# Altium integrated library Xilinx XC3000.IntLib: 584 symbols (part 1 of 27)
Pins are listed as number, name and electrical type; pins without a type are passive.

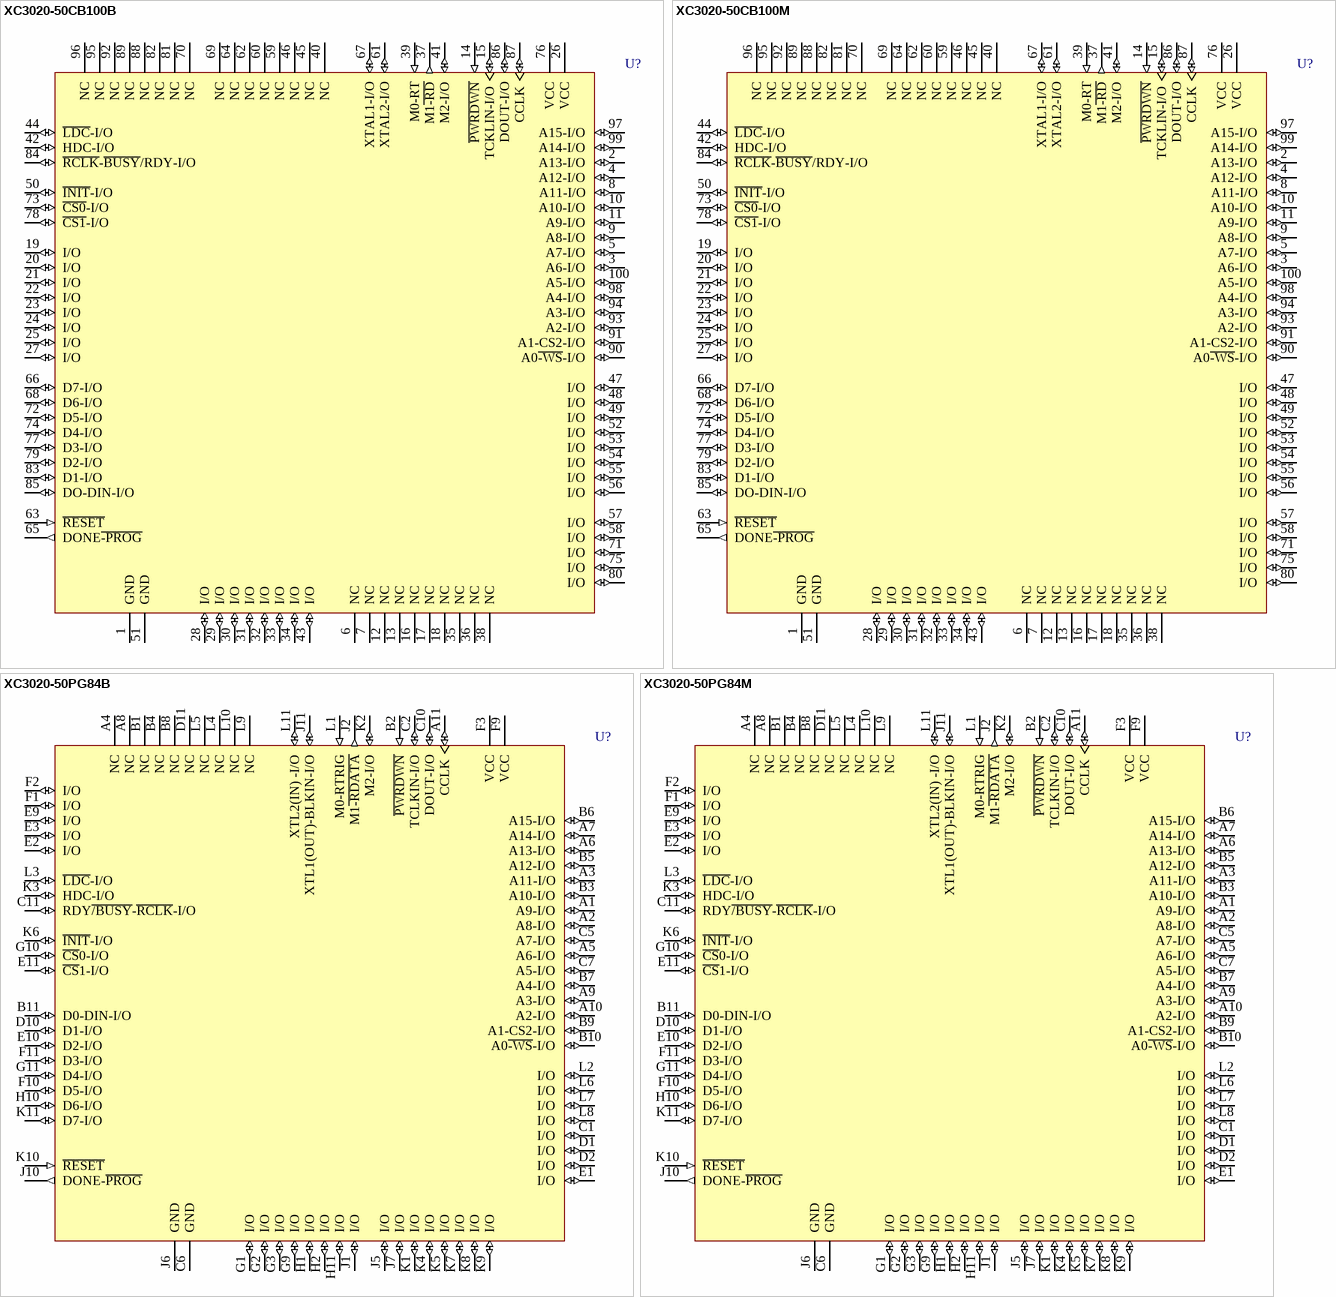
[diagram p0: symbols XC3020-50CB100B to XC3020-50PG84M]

## XC3020-50CB100B
designator U?
Logic Cell Array with 64 CLBs, with 64 I/O Pins, 100-Pin CQFP, Military Class B Grade; ComponentAvailability: Not for New Design
footprint CB100_N (CQFP, 100-Leads, Body 19x19mm; Pitch 0.635mm, Gullwing Leadform, IPC Medium Density)
footprint CB100_L (CQFP, 100-Leads, Body 19x19mm; Pitch 0.635mm, Gullwing Leadform, IPC High Density)
footprint CB100_M (CQFP, 100-Leads, Body 19x19mm; Pitch 0.635mm, Gullwing Leadform, IPC Low Density)
3D model XC3020-CB100 (100-Pin Ceramic Brazed Quad Flat Pack (CB100))
pins: 1 GND (power), 2 A13-I/O (io), 3 A6-I/O (io), 4 A12-I/O (io), 5 A7-I/O (io), 6 NC, 7 NC, 8 A11-I/O (io), 9 A8-I/O (io), 10 A10-I/O (io), 11 A9-I/O (io), 12 NC, 13 NC, 14 ~{PWRDWN} (in), 15 TCKLIN-I/O (io), 16 NC, 17 NC, 18 NC, 19 I/O (io), 20 I/O (io), 21 I/O (io), 22 I/O (io), 23 I/O (io), 24 I/O (io), 25 I/O (io), 26 VCC (power), 27 I/O (io), 28 I/O (io), 29 I/O (io), 30 I/O (io), 31 I/O (io), 32 I/O (io), 33 I/O (io), 34 I/O (io), 35 NC, 36 NC, 37 M1~{-RD} (out), 38 NC, 39 M0-RT (in), 40 NC, 41 M2-I/O (io), 42 HDC-I/O (io), 43 I/O (io), 44 ~{LDC}-I/O (io), 45 NC, 46 NC, 47 I/O (io), 48 I/O (io), 49 I/O (io), 50 ~{INIT}-I/O (io), 51 GND (power), 52 I/O (io), 53 I/O (io), 54 I/O (io), 55 I/O (io), 56 I/O (io), 57 I/O (io), 58 I/O (io), 59 NC, 60 NC, 61 XTAL2-I/O (io), 62 NC, 63 ~{RESET} (in), 64 NC, 65 DONE~{-PROG} (out), 66 D7-I/O (io), 67 XTAL1-I/O (io), 68 D6-I/O (io), 69 NC, 70 NC, 71 I/O (io), 72 D5-I/O (io), 73 ~{CS0}-I/O (io), 74 D4-I/O (io), 75 I/O (io), 76 VCC (power), 77 D3-I/O (io), 78 ~{CS1}-I/O (io), 79 D2-I/O (io), 80 I/O (io), 81 NC, 82 NC, 83 D1-I/O (io), 84 ~{RCLK}-~{BUSY}/RDY-I/O (io), 85 DO-DIN-I/O (io), 86 DOUT-I/O (io), 87 CCLK (io), 88 NC, 89 NC, 90 A0~{-WS}-I/O (io), 91 A1-CS2-I/O (io), 92 NC, 93 A2-I/O (io), 94 A3-I/O (io), 95 NC, 96 NC, 97 A15-I/O (io), 98 A4-I/O (io), 99 A14-I/O (io), 100 A5-I/O (io)

## XC3020-50CB100M
designator U?
Logic Cell Array with 64 CLBs, with 64 I/O Pins, 100-Pin CQFP, Military Grade; ComponentAvailability: Not for New Design
footprint CB100_N (CQFP, 100-Leads, Body 19x19mm; Pitch 0.635mm, Gullwing Leadform, IPC Medium Density)
footprint CB100_L (CQFP, 100-Leads, Body 19x19mm; Pitch 0.635mm, Gullwing Leadform, IPC High Density)
footprint CB100_M (CQFP, 100-Leads, Body 19x19mm; Pitch 0.635mm, Gullwing Leadform, IPC Low Density)
3D model XC3020-CB100 (100-Pin Ceramic Brazed Quad Flat Pack (CB100))
pins: 1 GND (power), 2 A13-I/O (io), 3 A6-I/O (io), 4 A12-I/O (io), 5 A7-I/O (io), 6 NC, 7 NC, 8 A11-I/O (io), 9 A8-I/O (io), 10 A10-I/O (io), 11 A9-I/O (io), 12 NC, 13 NC, 14 ~{PWRDWN} (in), 15 TCKLIN-I/O (io), 16 NC, 17 NC, 18 NC, 19 I/O (io), 20 I/O (io), 21 I/O (io), 22 I/O (io), 23 I/O (io), 24 I/O (io), 25 I/O (io), 26 VCC (power), 27 I/O (io), 28 I/O (io), 29 I/O (io), 30 I/O (io), 31 I/O (io), 32 I/O (io), 33 I/O (io), 34 I/O (io), 35 NC, 36 NC, 37 M1~{-RD} (out), 38 NC, 39 M0-RT (in), 40 NC, 41 M2-I/O (io), 42 HDC-I/O (io), 43 I/O (io), 44 ~{LDC}-I/O (io), 45 NC, 46 NC, 47 I/O (io), 48 I/O (io), 49 I/O (io), 50 ~{INIT}-I/O (io), 51 GND (power), 52 I/O (io), 53 I/O (io), 54 I/O (io), 55 I/O (io), 56 I/O (io), 57 I/O (io), 58 I/O (io), 59 NC, 60 NC, 61 XTAL2-I/O (io), 62 NC, 63 ~{RESET} (in), 64 NC, 65 DONE~{-PROG} (out), 66 D7-I/O (io), 67 XTAL1-I/O (io), 68 D6-I/O (io), 69 NC, 70 NC, 71 I/O (io), 72 D5-I/O (io), 73 ~{CS0}-I/O (io), 74 D4-I/O (io), 75 I/O (io), 76 VCC (power), 77 D3-I/O (io), 78 ~{CS1}-I/O (io), 79 D2-I/O (io), 80 I/O (io), 81 NC, 82 NC, 83 D1-I/O (io), 84 ~{RCLK}-~{BUSY}/RDY-I/O (io), 85 DO-DIN-I/O (io), 86 DOUT-I/O (io), 87 CCLK (io), 88 NC, 89 NC, 90 A0~{-WS}-I/O (io), 91 A1-CS2-I/O (io), 92 NC, 93 A2-I/O (io), 94 A3-I/O (io), 95 NC, 96 NC, 97 A15-I/O (io), 98 A4-I/O (io), 99 A14-I/O (io), 100 A5-I/O (io)

## XC3020-50PG84B
designator U?
Logic Cell Array with 64 CLBs, with 64 I/O Pins, 84-Pin PGA, Military Class B Grade; ComponentAvailability: Not for New Design
footprint PG84 (PGA, 85-Leads, Body 28x28mm, Pitch 2.54mm)
3D model XC3020-PG84 (84-Pin Ceramic Pin Grid Array (PG84))
pins: A1 A9-I/O (io), A2 A8-I/O (io), A3 A11-I/O (io), A4 NC, A5 A6-I/O (io), A6 A13-I/O (io), A7 A14-I/O (io), A8 NC, A9 A3-I/O (io), A10 A2-I/O (io), A11 CCLK (io), B1 NC, B2 ~{PWRDWN} (in), B3 A10-I/O (io), B4 NC, B5 A12-I/O (io), B6 A15-I/O (io), B7 A4-I/O (io), B8 NC, B9 A1-CS2-I/O (io), B10 A0~{-WS}-I/O (io), B11 D0-DIN-I/O (io), C1 I/O (io), C2 TCLKIN-I/O (io), C5 A7-I/O (io), C6 GND (power), C7 A5-I/O (io), C10 DOUT-I/O (io), C11 RDY~{/BUSY}-~{RCLK}-I/O (io), D1 I/O (io), D2 I/O (io), D10 D1-I/O (io), D11 NC, E1 I/O (io), E2 I/O (io), E3 I/O (io), E9 I/O (io), E10 D2-I/O (io), E11 ~{CS}1-I/O (io), F1 I/O (io), F2 I/O (io), F3 VCC (power), F9 VCC (power), F10 D5-I/O (io), F11 D3-I/O (io), G1 I/O (io), G2 I/O (io), G3 I/O (io), G9 I/O (io), G10 ~{CS}0-I/O (io), G11 D4-I/O (io), H1 I/O (io), H2 I/O (io), H10 D6-I/O (io), H11 I/O (io), J1 I/O (io), J2 M1~{-RDATA} (out), J5 I/O (io), J6 GND (power), J7 I/O (io), J10 DONE-~{PROG} (out), J11 XTL1(OUT)-BLKIN-I/O (io), K1 I/O (io), K2 M2-I/O (io), K3 HDC-I/O (io), K4 I/O (io), K5 I/O (io), K6 ~{INIT}-I/O (io), K7 I/O (io), K8 I/O (io), K9 I/O (io), K10 ~{RESET} (in), K11 D7-I/O (io), L1 M0-RTRIG (in), L2 I/O (io), L3 ~{LDC}-I/O (io), L4 NC, L5 NC, L6 I/O (io), L7 I/O (io), L8 I/O (io), L9 NC, L10 NC, L11 XTL2(IN) -I/O (io)

## XC3020-50PG84M
designator U?
Logic Cell Array with 64 CLBs, with 64 I/O Pins, 84-Pin PGA, Military Grade; ComponentAvailability: Not for New Design
footprint PG84 (PGA, 85-Leads, Body 28x28mm, Pitch 2.54mm)
3D model XC3020-PG84 (84-Pin Ceramic Pin Grid Array (PG84))
pins: A1 A9-I/O (io), A2 A8-I/O (io), A3 A11-I/O (io), A4 NC, A5 A6-I/O (io), A6 A13-I/O (io), A7 A14-I/O (io), A8 NC, A9 A3-I/O (io), A10 A2-I/O (io), A11 CCLK (io), B1 NC, B2 ~{PWRDWN} (in), B3 A10-I/O (io), B4 NC, B5 A12-I/O (io), B6 A15-I/O (io), B7 A4-I/O (io), B8 NC, B9 A1-CS2-I/O (io), B10 A0~{-WS}-I/O (io), B11 D0-DIN-I/O (io), C1 I/O (io), C2 TCLKIN-I/O (io), C5 A7-I/O (io), C6 GND (power), C7 A5-I/O (io), C10 DOUT-I/O (io), C11 RDY~{/BUSY}-~{RCLK}-I/O (io), D1 I/O (io), D2 I/O (io), D10 D1-I/O (io), D11 NC, E1 I/O (io), E2 I/O (io), E3 I/O (io), E9 I/O (io), E10 D2-I/O (io), E11 ~{CS}1-I/O (io), F1 I/O (io), F2 I/O (io), F3 VCC (power), F9 VCC (power), F10 D5-I/O (io), F11 D3-I/O (io), G1 I/O (io), G2 I/O (io), G3 I/O (io), G9 I/O (io), G10 ~{CS}0-I/O (io), G11 D4-I/O (io), H1 I/O (io), H2 I/O (io), H10 D6-I/O (io), H11 I/O (io), J1 I/O (io), J2 M1~{-RDATA} (out), J5 I/O (io), J6 GND (power), J7 I/O (io), J10 DONE-~{PROG} (out), J11 XTL1(OUT)-BLKIN-I/O (io), K1 I/O (io), K2 M2-I/O (io), K3 HDC-I/O (io), K4 I/O (io), K5 I/O (io), K6 ~{INIT}-I/O (io), K7 I/O (io), K8 I/O (io), K9 I/O (io), K10 ~{RESET} (in), K11 D7-I/O (io), L1 M0-RTRIG (in), L2 I/O (io), L3 ~{LDC}-I/O (io), L4 NC, L5 NC, L6 I/O (io), L7 I/O (io), L8 I/O (io), L9 NC, L10 NC, L11 XTL2(IN) -I/O (io)

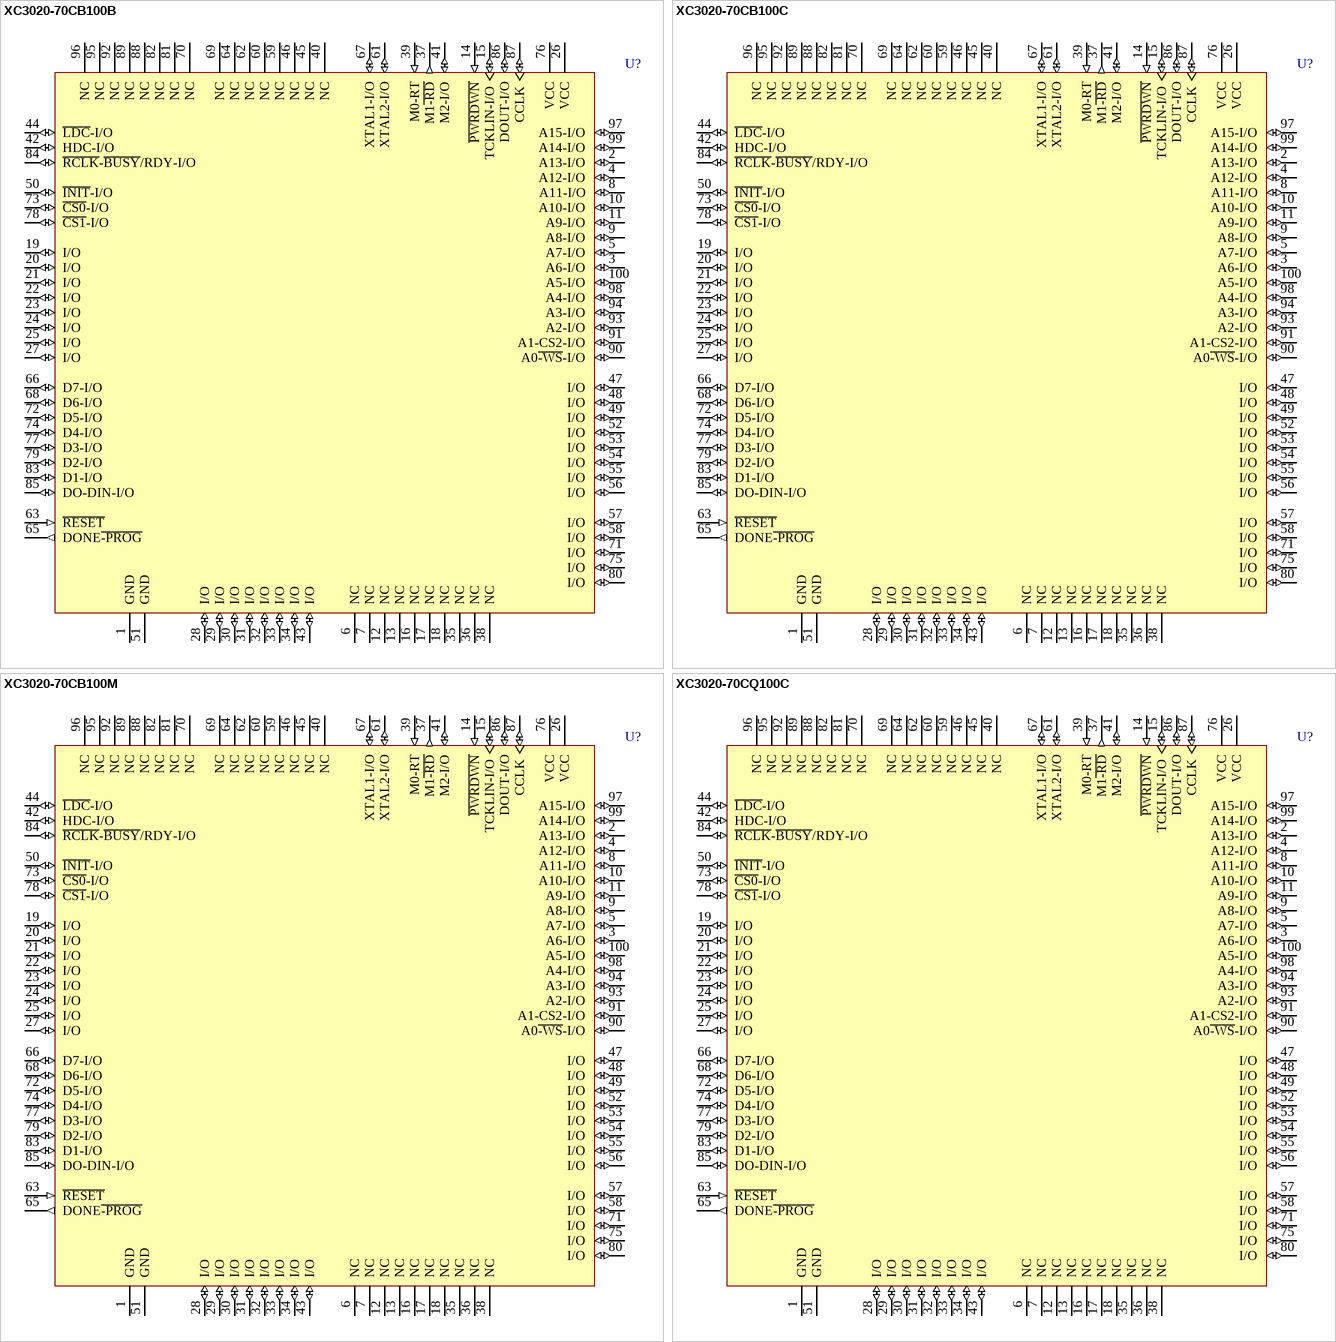
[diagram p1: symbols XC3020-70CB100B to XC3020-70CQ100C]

## XC3020-70CB100B
designator U?
Logic Cell Array with 64 CLBs, with 64 I/O Pins, 100-Pin CQFP, Military Class B Grade; ComponentAvailability: Not for New Design
footprint CB100_N (CQFP, 100-Leads, Body 19x19mm; Pitch 0.635mm, Gullwing Leadform, IPC Medium Density)
footprint CB100_L (CQFP, 100-Leads, Body 19x19mm; Pitch 0.635mm, Gullwing Leadform, IPC High Density)
footprint CB100_M (CQFP, 100-Leads, Body 19x19mm; Pitch 0.635mm, Gullwing Leadform, IPC Low Density)
3D model XC3020-CB100 (100-Pin Ceramic Brazed Quad Flat Pack (CB100))
pins: 1 GND (power), 2 A13-I/O (io), 3 A6-I/O (io), 4 A12-I/O (io), 5 A7-I/O (io), 6 NC, 7 NC, 8 A11-I/O (io), 9 A8-I/O (io), 10 A10-I/O (io), 11 A9-I/O (io), 12 NC, 13 NC, 14 ~{PWRDWN} (in), 15 TCKLIN-I/O (io), 16 NC, 17 NC, 18 NC, 19 I/O (io), 20 I/O (io), 21 I/O (io), 22 I/O (io), 23 I/O (io), 24 I/O (io), 25 I/O (io), 26 VCC (power), 27 I/O (io), 28 I/O (io), 29 I/O (io), 30 I/O (io), 31 I/O (io), 32 I/O (io), 33 I/O (io), 34 I/O (io), 35 NC, 36 NC, 37 M1~{-RD} (out), 38 NC, 39 M0-RT (in), 40 NC, 41 M2-I/O (io), 42 HDC-I/O (io), 43 I/O (io), 44 ~{LDC}-I/O (io), 45 NC, 46 NC, 47 I/O (io), 48 I/O (io), 49 I/O (io), 50 ~{INIT}-I/O (io), 51 GND (power), 52 I/O (io), 53 I/O (io), 54 I/O (io), 55 I/O (io), 56 I/O (io), 57 I/O (io), 58 I/O (io), 59 NC, 60 NC, 61 XTAL2-I/O (io), 62 NC, 63 ~{RESET} (in), 64 NC, 65 DONE~{-PROG} (out), 66 D7-I/O (io), 67 XTAL1-I/O (io), 68 D6-I/O (io), 69 NC, 70 NC, 71 I/O (io), 72 D5-I/O (io), 73 ~{CS0}-I/O (io), 74 D4-I/O (io), 75 I/O (io), 76 VCC (power), 77 D3-I/O (io), 78 ~{CS1}-I/O (io), 79 D2-I/O (io), 80 I/O (io), 81 NC, 82 NC, 83 D1-I/O (io), 84 ~{RCLK}-~{BUSY}/RDY-I/O (io), 85 DO-DIN-I/O (io), 86 DOUT-I/O (io), 87 CCLK (io), 88 NC, 89 NC, 90 A0~{-WS}-I/O (io), 91 A1-CS2-I/O (io), 92 NC, 93 A2-I/O (io), 94 A3-I/O (io), 95 NC, 96 NC, 97 A15-I/O (io), 98 A4-I/O (io), 99 A14-I/O (io), 100 A5-I/O (io)

## XC3020-70CB100C
designator U?
Logic Cell Array with 64 CLBs, with 64 I/O Pins, 100-Pin CQFP, Commercial Grade; ComponentAvailability: Not for New Design
footprint CB100_N (CQFP, 100-Leads, Body 19x19mm; Pitch 0.635mm, Gullwing Leadform, IPC Medium Density)
footprint CB100_L (CQFP, 100-Leads, Body 19x19mm; Pitch 0.635mm, Gullwing Leadform, IPC High Density)
footprint CB100_M (CQFP, 100-Leads, Body 19x19mm; Pitch 0.635mm, Gullwing Leadform, IPC Low Density)
3D model XC3020-CB100 (100-Pin Ceramic Brazed Quad Flat Pack (CB100))
pins: 1 GND (power), 2 A13-I/O (io), 3 A6-I/O (io), 4 A12-I/O (io), 5 A7-I/O (io), 6 NC, 7 NC, 8 A11-I/O (io), 9 A8-I/O (io), 10 A10-I/O (io), 11 A9-I/O (io), 12 NC, 13 NC, 14 ~{PWRDWN} (in), 15 TCKLIN-I/O (io), 16 NC, 17 NC, 18 NC, 19 I/O (io), 20 I/O (io), 21 I/O (io), 22 I/O (io), 23 I/O (io), 24 I/O (io), 25 I/O (io), 26 VCC (power), 27 I/O (io), 28 I/O (io), 29 I/O (io), 30 I/O (io), 31 I/O (io), 32 I/O (io), 33 I/O (io), 34 I/O (io), 35 NC, 36 NC, 37 M1~{-RD} (out), 38 NC, 39 M0-RT (in), 40 NC, 41 M2-I/O (io), 42 HDC-I/O (io), 43 I/O (io), 44 ~{LDC}-I/O (io), 45 NC, 46 NC, 47 I/O (io), 48 I/O (io), 49 I/O (io), 50 ~{INIT}-I/O (io), 51 GND (power), 52 I/O (io), 53 I/O (io), 54 I/O (io), 55 I/O (io), 56 I/O (io), 57 I/O (io), 58 I/O (io), 59 NC, 60 NC, 61 XTAL2-I/O (io), 62 NC, 63 ~{RESET} (in), 64 NC, 65 DONE~{-PROG} (out), 66 D7-I/O (io), 67 XTAL1-I/O (io), 68 D6-I/O (io), 69 NC, 70 NC, 71 I/O (io), 72 D5-I/O (io), 73 ~{CS0}-I/O (io), 74 D4-I/O (io), 75 I/O (io), 76 VCC (power), 77 D3-I/O (io), 78 ~{CS1}-I/O (io), 79 D2-I/O (io), 80 I/O (io), 81 NC, 82 NC, 83 D1-I/O (io), 84 ~{RCLK}-~{BUSY}/RDY-I/O (io), 85 DO-DIN-I/O (io), 86 DOUT-I/O (io), 87 CCLK (io), 88 NC, 89 NC, 90 A0~{-WS}-I/O (io), 91 A1-CS2-I/O (io), 92 NC, 93 A2-I/O (io), 94 A3-I/O (io), 95 NC, 96 NC, 97 A15-I/O (io), 98 A4-I/O (io), 99 A14-I/O (io), 100 A5-I/O (io)

## XC3020-70CB100M
designator U?
Logic Cell Array with 64 CLBs, with 64 I/O Pins, 100-Pin CQFP, Military Grade; ComponentAvailability: Not for New Design
footprint CB100_N (CQFP, 100-Leads, Body 19x19mm; Pitch 0.635mm, Gullwing Leadform, IPC Medium Density)
footprint CB100_L (CQFP, 100-Leads, Body 19x19mm; Pitch 0.635mm, Gullwing Leadform, IPC High Density)
footprint CB100_M (CQFP, 100-Leads, Body 19x19mm; Pitch 0.635mm, Gullwing Leadform, IPC Low Density)
3D model XC3020-CB100 (100-Pin Ceramic Brazed Quad Flat Pack (CB100))
pins: 1 GND (power), 2 A13-I/O (io), 3 A6-I/O (io), 4 A12-I/O (io), 5 A7-I/O (io), 6 NC, 7 NC, 8 A11-I/O (io), 9 A8-I/O (io), 10 A10-I/O (io), 11 A9-I/O (io), 12 NC, 13 NC, 14 ~{PWRDWN} (in), 15 TCKLIN-I/O (io), 16 NC, 17 NC, 18 NC, 19 I/O (io), 20 I/O (io), 21 I/O (io), 22 I/O (io), 23 I/O (io), 24 I/O (io), 25 I/O (io), 26 VCC (power), 27 I/O (io), 28 I/O (io), 29 I/O (io), 30 I/O (io), 31 I/O (io), 32 I/O (io), 33 I/O (io), 34 I/O (io), 35 NC, 36 NC, 37 M1~{-RD} (out), 38 NC, 39 M0-RT (in), 40 NC, 41 M2-I/O (io), 42 HDC-I/O (io), 43 I/O (io), 44 ~{LDC}-I/O (io), 45 NC, 46 NC, 47 I/O (io), 48 I/O (io), 49 I/O (io), 50 ~{INIT}-I/O (io), 51 GND (power), 52 I/O (io), 53 I/O (io), 54 I/O (io), 55 I/O (io), 56 I/O (io), 57 I/O (io), 58 I/O (io), 59 NC, 60 NC, 61 XTAL2-I/O (io), 62 NC, 63 ~{RESET} (in), 64 NC, 65 DONE~{-PROG} (out), 66 D7-I/O (io), 67 XTAL1-I/O (io), 68 D6-I/O (io), 69 NC, 70 NC, 71 I/O (io), 72 D5-I/O (io), 73 ~{CS0}-I/O (io), 74 D4-I/O (io), 75 I/O (io), 76 VCC (power), 77 D3-I/O (io), 78 ~{CS1}-I/O (io), 79 D2-I/O (io), 80 I/O (io), 81 NC, 82 NC, 83 D1-I/O (io), 84 ~{RCLK}-~{BUSY}/RDY-I/O (io), 85 DO-DIN-I/O (io), 86 DOUT-I/O (io), 87 CCLK (io), 88 NC, 89 NC, 90 A0~{-WS}-I/O (io), 91 A1-CS2-I/O (io), 92 NC, 93 A2-I/O (io), 94 A3-I/O (io), 95 NC, 96 NC, 97 A15-I/O (io), 98 A4-I/O (io), 99 A14-I/O (io), 100 A5-I/O (io)

## XC3020-70CQ100C
designator U?
Logic Cell Array with 64 CLBs, with 64 I/O Pins, 100-Pin CQFP, Commercial Grade; ComponentAvailability: Not for New Design
footprint CB100_N (CQFP, 100-Leads, Body 19x19mm; Pitch 0.635mm, Gullwing Leadform, IPC Medium Density)
footprint CB100_L (CQFP, 100-Leads, Body 19x19mm; Pitch 0.635mm, Gullwing Leadform, IPC High Density)
footprint CB100_M (CQFP, 100-Leads, Body 19x19mm; Pitch 0.635mm, Gullwing Leadform, IPC Low Density)
3D model XC3020-CB100 (100-Pin Ceramic Brazed Quad Flat Pack (CB100))
pins: 1 GND (power), 2 A13-I/O (io), 3 A6-I/O (io), 4 A12-I/O (io), 5 A7-I/O (io), 6 NC, 7 NC, 8 A11-I/O (io), 9 A8-I/O (io), 10 A10-I/O (io), 11 A9-I/O (io), 12 NC, 13 NC, 14 ~{PWRDWN} (in), 15 TCKLIN-I/O (io), 16 NC, 17 NC, 18 NC, 19 I/O (io), 20 I/O (io), 21 I/O (io), 22 I/O (io), 23 I/O (io), 24 I/O (io), 25 I/O (io), 26 VCC (power), 27 I/O (io), 28 I/O (io), 29 I/O (io), 30 I/O (io), 31 I/O (io), 32 I/O (io), 33 I/O (io), 34 I/O (io), 35 NC, 36 NC, 37 M1~{-RD} (out), 38 NC, 39 M0-RT (in), 40 NC, 41 M2-I/O (io), 42 HDC-I/O (io), 43 I/O (io), 44 ~{LDC}-I/O (io), 45 NC, 46 NC, 47 I/O (io), 48 I/O (io), 49 I/O (io), 50 ~{INIT}-I/O (io), 51 GND (power), 52 I/O (io), 53 I/O (io), 54 I/O (io), 55 I/O (io), 56 I/O (io), 57 I/O (io), 58 I/O (io), 59 NC, 60 NC, 61 XTAL2-I/O (io), 62 NC, 63 ~{RESET} (in), 64 NC, 65 DONE~{-PROG} (out), 66 D7-I/O (io), 67 XTAL1-I/O (io), 68 D6-I/O (io), 69 NC, 70 NC, 71 I/O (io), 72 D5-I/O (io), 73 ~{CS0}-I/O (io), 74 D4-I/O (io), 75 I/O (io), 76 VCC (power), 77 D3-I/O (io), 78 ~{CS1}-I/O (io), 79 D2-I/O (io), 80 I/O (io), 81 NC, 82 NC, 83 D1-I/O (io), 84 ~{RCLK}-~{BUSY}/RDY-I/O (io), 85 DO-DIN-I/O (io), 86 DOUT-I/O (io), 87 CCLK (io), 88 NC, 89 NC, 90 A0~{-WS}-I/O (io), 91 A1-CS2-I/O (io), 92 NC, 93 A2-I/O (io), 94 A3-I/O (io), 95 NC, 96 NC, 97 A15-I/O (io), 98 A4-I/O (io), 99 A14-I/O (io), 100 A5-I/O (io)

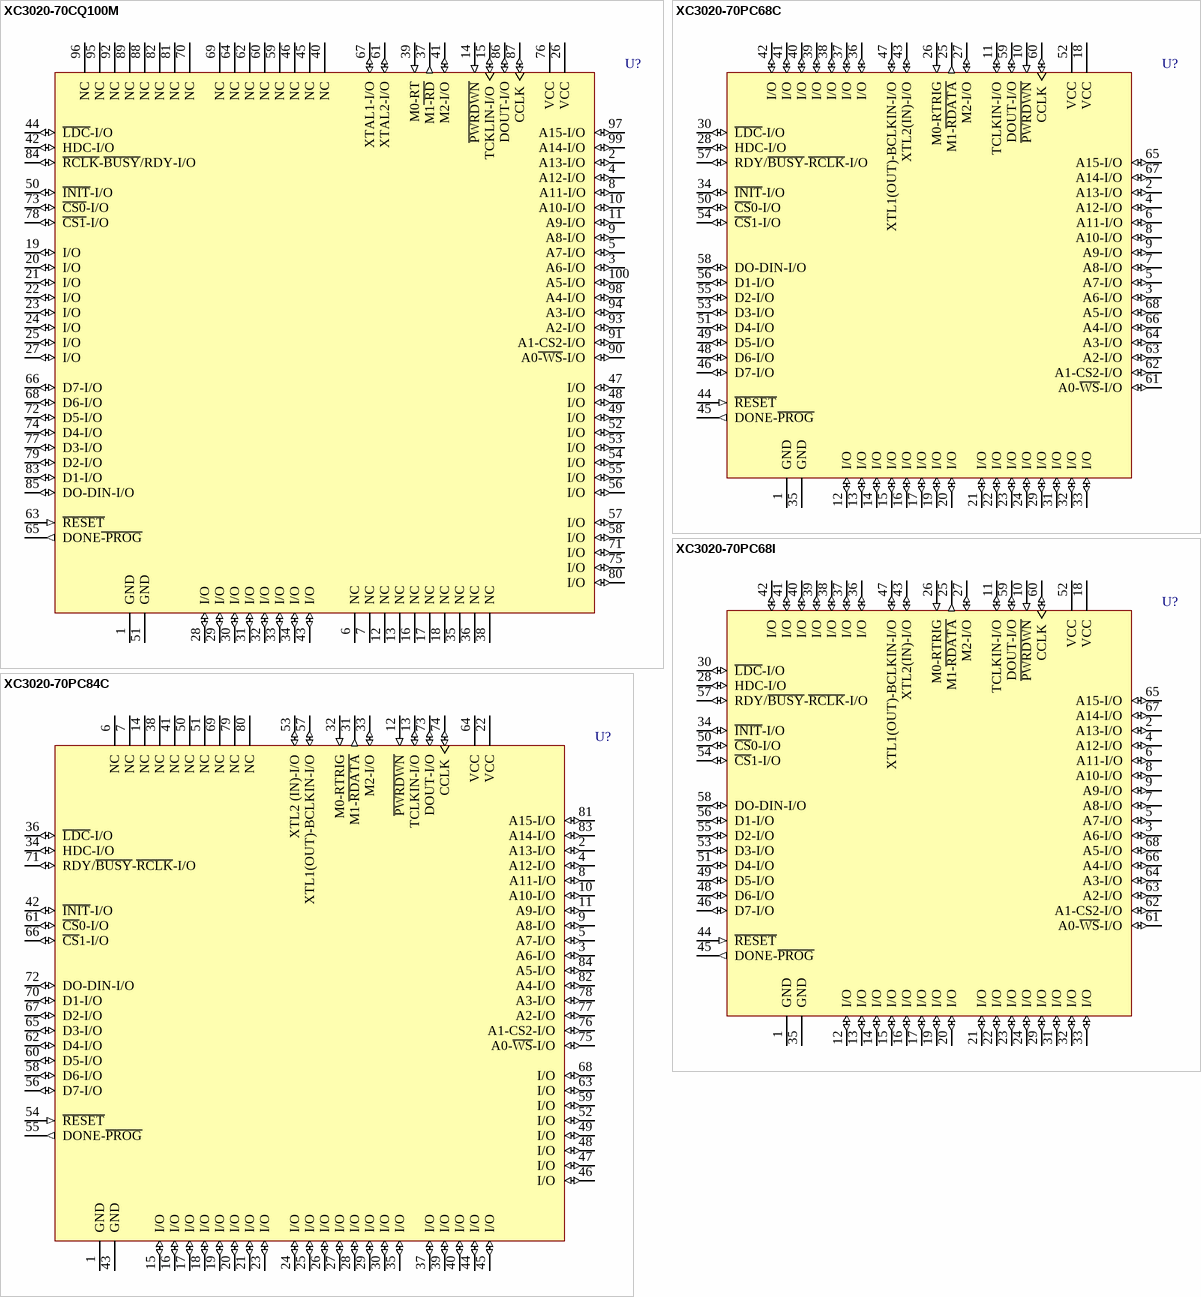
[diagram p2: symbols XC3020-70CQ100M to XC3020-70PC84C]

## XC3020-70CQ100M
designator U?
Logic Cell Array with 64 CLBs, with 64 I/O Pins, 100-Pin CQFP, Military Grade; ComponentAvailability: Not for New Design
footprint CB100_N (CQFP, 100-Leads, Body 19x19mm; Pitch 0.635mm, Gullwing Leadform, IPC Medium Density)
footprint CB100_L (CQFP, 100-Leads, Body 19x19mm; Pitch 0.635mm, Gullwing Leadform, IPC High Density)
footprint CB100_M (CQFP, 100-Leads, Body 19x19mm; Pitch 0.635mm, Gullwing Leadform, IPC Low Density)
3D model XC3020-CB100 (100-Pin Ceramic Brazed Quad Flat Pack (CB100))
pins: 1 GND (power), 2 A13-I/O (io), 3 A6-I/O (io), 4 A12-I/O (io), 5 A7-I/O (io), 6 NC, 7 NC, 8 A11-I/O (io), 9 A8-I/O (io), 10 A10-I/O (io), 11 A9-I/O (io), 12 NC, 13 NC, 14 ~{PWRDWN} (in), 15 TCKLIN-I/O (io), 16 NC, 17 NC, 18 NC, 19 I/O (io), 20 I/O (io), 21 I/O (io), 22 I/O (io), 23 I/O (io), 24 I/O (io), 25 I/O (io), 26 VCC (power), 27 I/O (io), 28 I/O (io), 29 I/O (io), 30 I/O (io), 31 I/O (io), 32 I/O (io), 33 I/O (io), 34 I/O (io), 35 NC, 36 NC, 37 M1~{-RD} (out), 38 NC, 39 M0-RT (in), 40 NC, 41 M2-I/O (io), 42 HDC-I/O (io), 43 I/O (io), 44 ~{LDC}-I/O (io), 45 NC, 46 NC, 47 I/O (io), 48 I/O (io), 49 I/O (io), 50 ~{INIT}-I/O (io), 51 GND (power), 52 I/O (io), 53 I/O (io), 54 I/O (io), 55 I/O (io), 56 I/O (io), 57 I/O (io), 58 I/O (io), 59 NC, 60 NC, 61 XTAL2-I/O (io), 62 NC, 63 ~{RESET} (in), 64 NC, 65 DONE~{-PROG} (out), 66 D7-I/O (io), 67 XTAL1-I/O (io), 68 D6-I/O (io), 69 NC, 70 NC, 71 I/O (io), 72 D5-I/O (io), 73 ~{CS0}-I/O (io), 74 D4-I/O (io), 75 I/O (io), 76 VCC (power), 77 D3-I/O (io), 78 ~{CS1}-I/O (io), 79 D2-I/O (io), 80 I/O (io), 81 NC, 82 NC, 83 D1-I/O (io), 84 ~{RCLK}-~{BUSY}/RDY-I/O (io), 85 DO-DIN-I/O (io), 86 DOUT-I/O (io), 87 CCLK (io), 88 NC, 89 NC, 90 A0~{-WS}-I/O (io), 91 A1-CS2-I/O (io), 92 NC, 93 A2-I/O (io), 94 A3-I/O (io), 95 NC, 96 NC, 97 A15-I/O (io), 98 A4-I/O (io), 99 A14-I/O (io), 100 A5-I/O (io)

## XC3020-70PC68C
designator U?
Logic Cell Array with 64 CLBs, with 58 I/O Pins, 68-Pin PLCC, Commercial Grade; ComponentAvailability: Not for New Design
footprint PC68_N (Leaded Chip Carrier, 68-Leads, Body 24x24mm, Pitch 1.27mm, IPC Medium Density)
footprint PC68_L (Leaded Chip Carrier, 68-Leads, Body 24x24mm, Pitch 1.27mm, IPC High Density)
footprint PC68_M (Leaded Chip Carrier, 68-Leads, Body 24x24mm, Pitch 1.27mm, IPC Low Density)
3D model XC3020-PC68 (68-Pin Plastic Leaded Chip Carrier (PC68))
pins: 1 GND (power), 2 A13-I/O (io), 3 A6-I/O (io), 4 A12-I/O (io), 5 A7-I/O (io), 6 A11-I/O (io), 7 A8-I/O (io), 8 A10-I/O (io), 9 A9-I/O (io), 10 ~{PWRDWN} (in), 11 TCLKIN-I/O (io), 12 I/O (io), 13 I/O (io), 14 I/O (io), 15 I/O (io), 16 I/O (io), 17 I/O (io), 18 VCC (power), 19 I/O (io), 20 I/O (io), 21 I/O (io), 22 I/O (io), 23 I/O (io), 24 I/O (io), 25 M1-~{RDATA} (out), 26 M0-RTRIG (in), 27 M2-I/O (io), 28 HDC-I/O (io), 29 I/O (io), 30 ~{LDC}-I/O (io), 31 I/O (io), 32 I/O (io), 33 I/O (io), 34 ~{INIT}-I/O (io), 35 GND (power), 36 I/O (io), 37 I/O (io), 38 I/O (io), 39 I/O (io), 40 I/O (io), 41 I/O (io), 42 I/O (io), 43 XTL2(IN)-I/O (io), 44 ~{RESET} (in), 45 DONE-~{PROG} (out), 46 D7-I/O (io), 47 XTL1(OUT)-BCLKIN-I/O (io), 48 D6-I/O (io), 49 D5-I/O (io), 50 ~{CS}0-I/O (io), 51 D4-I/O (io), 52 VCC (power), 53 D3-I/O (io), 54 ~{CS}1-I/O (io), 55 D2-I/O (io), 56 D1-I/O (io), 57 RDY/~{BUSY}-~{RCLK}-I/O (io), 58 DO-DIN-I/O (io), 59 DOUT-I/O (io), 60 CCLK (io), 61 A0-~{WS}-I/O (io), 62 A1-CS2-I/O (io), 63 A2-I/O (io), 64 A3-I/O (io), 65 A15-I/O (io), 66 A4-I/O (io), 67 A14-I/O (io), 68 A5-I/O (io)

## XC3020-70PC68I
designator U?
Logic Cell Array with 64 CLBs, with 58 I/O Pins, 68-Pin PLCC, Industrial Grade; ComponentAvailability: Not for New Design
footprint PC68_N (Leaded Chip Carrier, 68-Leads, Body 24x24mm, Pitch 1.27mm, IPC Medium Density)
footprint PC68_L (Leaded Chip Carrier, 68-Leads, Body 24x24mm, Pitch 1.27mm, IPC High Density)
footprint PC68_M (Leaded Chip Carrier, 68-Leads, Body 24x24mm, Pitch 1.27mm, IPC Low Density)
3D model XC3020-PC68 (68-Pin Plastic Leaded Chip Carrier (PC68))
pins: 1 GND (power), 2 A13-I/O (io), 3 A6-I/O (io), 4 A12-I/O (io), 5 A7-I/O (io), 6 A11-I/O (io), 7 A8-I/O (io), 8 A10-I/O (io), 9 A9-I/O (io), 10 ~{PWRDWN} (in), 11 TCLKIN-I/O (io), 12 I/O (io), 13 I/O (io), 14 I/O (io), 15 I/O (io), 16 I/O (io), 17 I/O (io), 18 VCC (power), 19 I/O (io), 20 I/O (io), 21 I/O (io), 22 I/O (io), 23 I/O (io), 24 I/O (io), 25 M1-~{RDATA} (out), 26 M0-RTRIG (in), 27 M2-I/O (io), 28 HDC-I/O (io), 29 I/O (io), 30 ~{LDC}-I/O (io), 31 I/O (io), 32 I/O (io), 33 I/O (io), 34 ~{INIT}-I/O (io), 35 GND (power), 36 I/O (io), 37 I/O (io), 38 I/O (io), 39 I/O (io), 40 I/O (io), 41 I/O (io), 42 I/O (io), 43 XTL2(IN)-I/O (io), 44 ~{RESET} (in), 45 DONE-~{PROG} (out), 46 D7-I/O (io), 47 XTL1(OUT)-BCLKIN-I/O (io), 48 D6-I/O (io), 49 D5-I/O (io), 50 ~{CS}0-I/O (io), 51 D4-I/O (io), 52 VCC (power), 53 D3-I/O (io), 54 ~{CS}1-I/O (io), 55 D2-I/O (io), 56 D1-I/O (io), 57 RDY/~{BUSY}-~{RCLK}-I/O (io), 58 DO-DIN-I/O (io), 59 DOUT-I/O (io), 60 CCLK (io), 61 A0-~{WS}-I/O (io), 62 A1-CS2-I/O (io), 63 A2-I/O (io), 64 A3-I/O (io), 65 A15-I/O (io), 66 A4-I/O (io), 67 A14-I/O (io), 68 A5-I/O (io)

## XC3020-70PC84C
designator U?
Logic Cell Array with 64 CLBs, with 64 I/O Pins, 84-Pin PLCC, Commercial Grade; ComponentAvailability: Not for New Design
footprint PC84_N (Leaded Chip Carrier, 84-Leads, Body 29.3x29.3mm, Pitch 1.27mm, IPC Medium Density)
footprint PC84_L (Leaded Chip Carrier, 84-Leads, Body 29.3x29.3mm, Pitch 1.27mm, IPC High Density)
footprint PC84_M (Leaded Chip Carrier, 84-Leads, Body 29.3x29.3mm, Pitch 1.27mm, IPC Low Density)
3D model XC3020-PC84 (84-Pin Plastic Leaded Chip Carrier (PC84))
pins: 1 GND (power), 2 A13-I/O (io), 3 A6-I/O (io), 4 A12-I/O (io), 5 A7-I/O (io), 6 NC, 7 NC, 8 A11-I/O (io), 9 A8-I/O (io), 10 A10-I/O (io), 11 A9-I/O (io), 12 ~{PWRDWN} (in), 13 TCLKIN-I/O (io), 14 NC, 15 I/O (io), 16 I/O (io), 17 I/O (io), 18 I/O (io), 19 I/O (io), 20 I/O (io), 21 I/O (io), 22 VCC (power), 23 I/O (io), 24 I/O (io), 25 I/O (io), 26 I/O (io), 27 I/O (io), 28 I/O (io), 29 I/O (io), 30 I/O (io), 31 M1-~{RDATA} (out), 32 M0-RTRIG (in), 33 M2-I/O (io), 34 HDC-I/O (io), 35 I/O (io), 36 ~{LDC}-I/O (io), 37 I/O (io), 38 NC, 39 I/O (io), 40 I/O (io), 41 NC, 42 ~{INIT}-I/O (io), 43 GND (power), 44 I/O (io), 45 I/O (io), 46 I/O (io), 47 I/O (io), 48 I/O (io), 49 I/O (io), 50 NC, 51 NC, 52 I/O (io), 53 XTL2 (IN)-I/O (io), 54 ~{RESET} (in), 55 DONE-~{PROG} (out), 56 D7-I/O (io), 57 XTL1(OUT)-BCLKIN-I/O (io), 58 D6-I/O (io), 59 I/O (io), 60 D5-I/O (io), 61 ~{CS}0-I/O (io), 62 D4-I/O (io), 63 I/O (io), 64 VCC (power), 65 D3-I/O (io), 66 ~{CS}1-I/O (io), 67 D2-I/O (io), 68 I/O (io), 69 NC, 70 D1-I/O (io), 71 RDY/~{BUSY}-~{RCLK}-I/O (io), 72 DO-DIN-I/O (io), 73 DOUT-I/O (io), 74 CCLK (io), 75 A0-~{WS}-I/O (io), 76 A1-CS2-I/O (io), 77 A2-I/O (io), 78 A3-I/O (io), 79 NC, 80 NC, 81 A15-I/O (io), 82 A4-I/O (io), 83 A14-I/O (io), 84 A5-I/O (io)

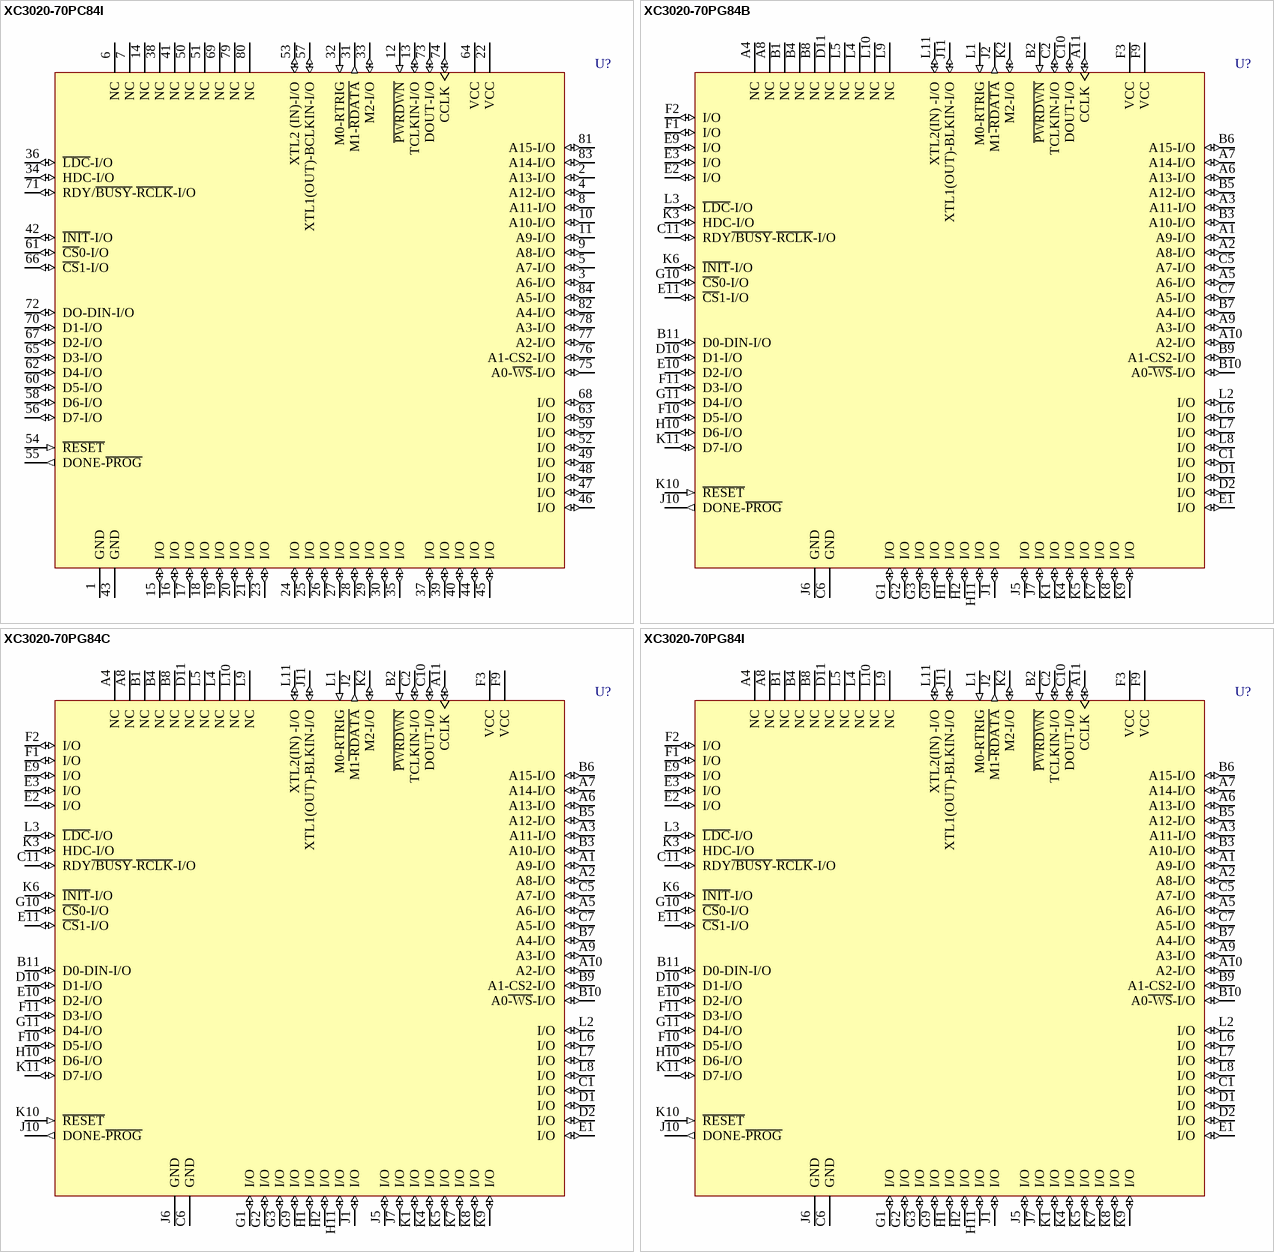
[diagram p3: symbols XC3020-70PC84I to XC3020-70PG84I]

## XC3020-70PC84I
designator U?
Logic Cell Array with 64 CLBs, with 64 I/O Pins, 84-Pin PLCC, Industrial Grade; ComponentAvailability: Not for New Design
footprint PC84_N (Leaded Chip Carrier, 84-Leads, Body 29.3x29.3mm, Pitch 1.27mm, IPC Medium Density)
footprint PC84_L (Leaded Chip Carrier, 84-Leads, Body 29.3x29.3mm, Pitch 1.27mm, IPC High Density)
footprint PC84_M (Leaded Chip Carrier, 84-Leads, Body 29.3x29.3mm, Pitch 1.27mm, IPC Low Density)
3D model XC3020-PC84 (84-Pin Plastic Leaded Chip Carrier (PC84))
pins: 1 GND (power), 2 A13-I/O (io), 3 A6-I/O (io), 4 A12-I/O (io), 5 A7-I/O (io), 6 NC, 7 NC, 8 A11-I/O (io), 9 A8-I/O (io), 10 A10-I/O (io), 11 A9-I/O (io), 12 ~{PWRDWN} (in), 13 TCLKIN-I/O (io), 14 NC, 15 I/O (io), 16 I/O (io), 17 I/O (io), 18 I/O (io), 19 I/O (io), 20 I/O (io), 21 I/O (io), 22 VCC (power), 23 I/O (io), 24 I/O (io), 25 I/O (io), 26 I/O (io), 27 I/O (io), 28 I/O (io), 29 I/O (io), 30 I/O (io), 31 M1-~{RDATA} (out), 32 M0-RTRIG (in), 33 M2-I/O (io), 34 HDC-I/O (io), 35 I/O (io), 36 ~{LDC}-I/O (io), 37 I/O (io), 38 NC, 39 I/O (io), 40 I/O (io), 41 NC, 42 ~{INIT}-I/O (io), 43 GND (power), 44 I/O (io), 45 I/O (io), 46 I/O (io), 47 I/O (io), 48 I/O (io), 49 I/O (io), 50 NC, 51 NC, 52 I/O (io), 53 XTL2 (IN)-I/O (io), 54 ~{RESET} (in), 55 DONE-~{PROG} (out), 56 D7-I/O (io), 57 XTL1(OUT)-BCLKIN-I/O (io), 58 D6-I/O (io), 59 I/O (io), 60 D5-I/O (io), 61 ~{CS}0-I/O (io), 62 D4-I/O (io), 63 I/O (io), 64 VCC (power), 65 D3-I/O (io), 66 ~{CS}1-I/O (io), 67 D2-I/O (io), 68 I/O (io), 69 NC, 70 D1-I/O (io), 71 RDY/~{BUSY}-~{RCLK}-I/O (io), 72 DO-DIN-I/O (io), 73 DOUT-I/O (io), 74 CCLK (io), 75 A0-~{WS}-I/O (io), 76 A1-CS2-I/O (io), 77 A2-I/O (io), 78 A3-I/O (io), 79 NC, 80 NC, 81 A15-I/O (io), 82 A4-I/O (io), 83 A14-I/O (io), 84 A5-I/O (io)

## XC3020-70PG84B
designator U?
Logic Cell Array with 64 CLBs, with 64 I/O Pins, 84-Pin PGA, Military Class B Grade; ComponentAvailability: Not for New Design
footprint PG84 (PGA, 85-Leads, Body 28x28mm, Pitch 2.54mm)
3D model XC3020-PG84 (84-Pin Ceramic Pin Grid Array (PG84))
pins: A1 A9-I/O (io), A2 A8-I/O (io), A3 A11-I/O (io), A4 NC, A5 A6-I/O (io), A6 A13-I/O (io), A7 A14-I/O (io), A8 NC, A9 A3-I/O (io), A10 A2-I/O (io), A11 CCLK (io), B1 NC, B2 ~{PWRDWN} (in), B3 A10-I/O (io), B4 NC, B5 A12-I/O (io), B6 A15-I/O (io), B7 A4-I/O (io), B8 NC, B9 A1-CS2-I/O (io), B10 A0~{-WS}-I/O (io), B11 D0-DIN-I/O (io), C1 I/O (io), C2 TCLKIN-I/O (io), C5 A7-I/O (io), C6 GND (power), C7 A5-I/O (io), C10 DOUT-I/O (io), C11 RDY~{/BUSY}-~{RCLK}-I/O (io), D1 I/O (io), D2 I/O (io), D10 D1-I/O (io), D11 NC, E1 I/O (io), E2 I/O (io), E3 I/O (io), E9 I/O (io), E10 D2-I/O (io), E11 ~{CS}1-I/O (io), F1 I/O (io), F2 I/O (io), F3 VCC (power), F9 VCC (power), F10 D5-I/O (io), F11 D3-I/O (io), G1 I/O (io), G2 I/O (io), G3 I/O (io), G9 I/O (io), G10 ~{CS}0-I/O (io), G11 D4-I/O (io), H1 I/O (io), H2 I/O (io), H10 D6-I/O (io), H11 I/O (io), J1 I/O (io), J2 M1~{-RDATA} (out), J5 I/O (io), J6 GND (power), J7 I/O (io), J10 DONE-~{PROG} (out), J11 XTL1(OUT)-BLKIN-I/O (io), K1 I/O (io), K2 M2-I/O (io), K3 HDC-I/O (io), K4 I/O (io), K5 I/O (io), K6 ~{INIT}-I/O (io), K7 I/O (io), K8 I/O (io), K9 I/O (io), K10 ~{RESET} (in), K11 D7-I/O (io), L1 M0-RTRIG (in), L2 I/O (io), L3 ~{LDC}-I/O (io), L4 NC, L5 NC, L6 I/O (io), L7 I/O (io), L8 I/O (io), L9 NC, L10 NC, L11 XTL2(IN) -I/O (io)

## XC3020-70PG84C
designator U?
Logic Cell Array with 64 CLBs, with 64 I/O Pins, 84-Pin PGA, Commercial Grade; ComponentAvailability: Not for New Design
footprint PG84 (PGA, 85-Leads, Body 28x28mm, Pitch 2.54mm)
3D model XC3020-PG84 (84-Pin Ceramic Pin Grid Array (PG84))
pins: A1 A9-I/O (io), A2 A8-I/O (io), A3 A11-I/O (io), A4 NC, A5 A6-I/O (io), A6 A13-I/O (io), A7 A14-I/O (io), A8 NC, A9 A3-I/O (io), A10 A2-I/O (io), A11 CCLK (io), B1 NC, B2 ~{PWRDWN} (in), B3 A10-I/O (io), B4 NC, B5 A12-I/O (io), B6 A15-I/O (io), B7 A4-I/O (io), B8 NC, B9 A1-CS2-I/O (io), B10 A0~{-WS}-I/O (io), B11 D0-DIN-I/O (io), C1 I/O (io), C2 TCLKIN-I/O (io), C5 A7-I/O (io), C6 GND (power), C7 A5-I/O (io), C10 DOUT-I/O (io), C11 RDY~{/BUSY}-~{RCLK}-I/O (io), D1 I/O (io), D2 I/O (io), D10 D1-I/O (io), D11 NC, E1 I/O (io), E2 I/O (io), E3 I/O (io), E9 I/O (io), E10 D2-I/O (io), E11 ~{CS}1-I/O (io), F1 I/O (io), F2 I/O (io), F3 VCC (power), F9 VCC (power), F10 D5-I/O (io), F11 D3-I/O (io), G1 I/O (io), G2 I/O (io), G3 I/O (io), G9 I/O (io), G10 ~{CS}0-I/O (io), G11 D4-I/O (io), H1 I/O (io), H2 I/O (io), H10 D6-I/O (io), H11 I/O (io), J1 I/O (io), J2 M1~{-RDATA} (out), J5 I/O (io), J6 GND (power), J7 I/O (io), J10 DONE-~{PROG} (out), J11 XTL1(OUT)-BLKIN-I/O (io), K1 I/O (io), K2 M2-I/O (io), K3 HDC-I/O (io), K4 I/O (io), K5 I/O (io), K6 ~{INIT}-I/O (io), K7 I/O (io), K8 I/O (io), K9 I/O (io), K10 ~{RESET} (in), K11 D7-I/O (io), L1 M0-RTRIG (in), L2 I/O (io), L3 ~{LDC}-I/O (io), L4 NC, L5 NC, L6 I/O (io), L7 I/O (io), L8 I/O (io), L9 NC, L10 NC, L11 XTL2(IN) -I/O (io)

## XC3020-70PG84I
designator U?
Logic Cell Array with 64 CLBs, with 64 I/O Pins, 84-Pin PGA, Industrial Grade; ComponentAvailability: Not for New Design
footprint PG84 (PGA, 85-Leads, Body 28x28mm, Pitch 2.54mm)
3D model XC3020-PG84 (84-Pin Ceramic Pin Grid Array (PG84))
pins: A1 A9-I/O (io), A2 A8-I/O (io), A3 A11-I/O (io), A4 NC, A5 A6-I/O (io), A6 A13-I/O (io), A7 A14-I/O (io), A8 NC, A9 A3-I/O (io), A10 A2-I/O (io), A11 CCLK (io), B1 NC, B2 ~{PWRDWN} (in), B3 A10-I/O (io), B4 NC, B5 A12-I/O (io), B6 A15-I/O (io), B7 A4-I/O (io), B8 NC, B9 A1-CS2-I/O (io), B10 A0~{-WS}-I/O (io), B11 D0-DIN-I/O (io), C1 I/O (io), C2 TCLKIN-I/O (io), C5 A7-I/O (io), C6 GND (power), C7 A5-I/O (io), C10 DOUT-I/O (io), C11 RDY~{/BUSY}-~{RCLK}-I/O (io), D1 I/O (io), D2 I/O (io), D10 D1-I/O (io), D11 NC, E1 I/O (io), E2 I/O (io), E3 I/O (io), E9 I/O (io), E10 D2-I/O (io), E11 ~{CS}1-I/O (io), F1 I/O (io), F2 I/O (io), F3 VCC (power), F9 VCC (power), F10 D5-I/O (io), F11 D3-I/O (io), G1 I/O (io), G2 I/O (io), G3 I/O (io), G9 I/O (io), G10 ~{CS}0-I/O (io), G11 D4-I/O (io), H1 I/O (io), H2 I/O (io), H10 D6-I/O (io), H11 I/O (io), J1 I/O (io), J2 M1~{-RDATA} (out), J5 I/O (io), J6 GND (power), J7 I/O (io), J10 DONE-~{PROG} (out), J11 XTL1(OUT)-BLKIN-I/O (io), K1 I/O (io), K2 M2-I/O (io), K3 HDC-I/O (io), K4 I/O (io), K5 I/O (io), K6 ~{INIT}-I/O (io), K7 I/O (io), K8 I/O (io), K9 I/O (io), K10 ~{RESET} (in), K11 D7-I/O (io), L1 M0-RTRIG (in), L2 I/O (io), L3 ~{LDC}-I/O (io), L4 NC, L5 NC, L6 I/O (io), L7 I/O (io), L8 I/O (io), L9 NC, L10 NC, L11 XTL2(IN) -I/O (io)

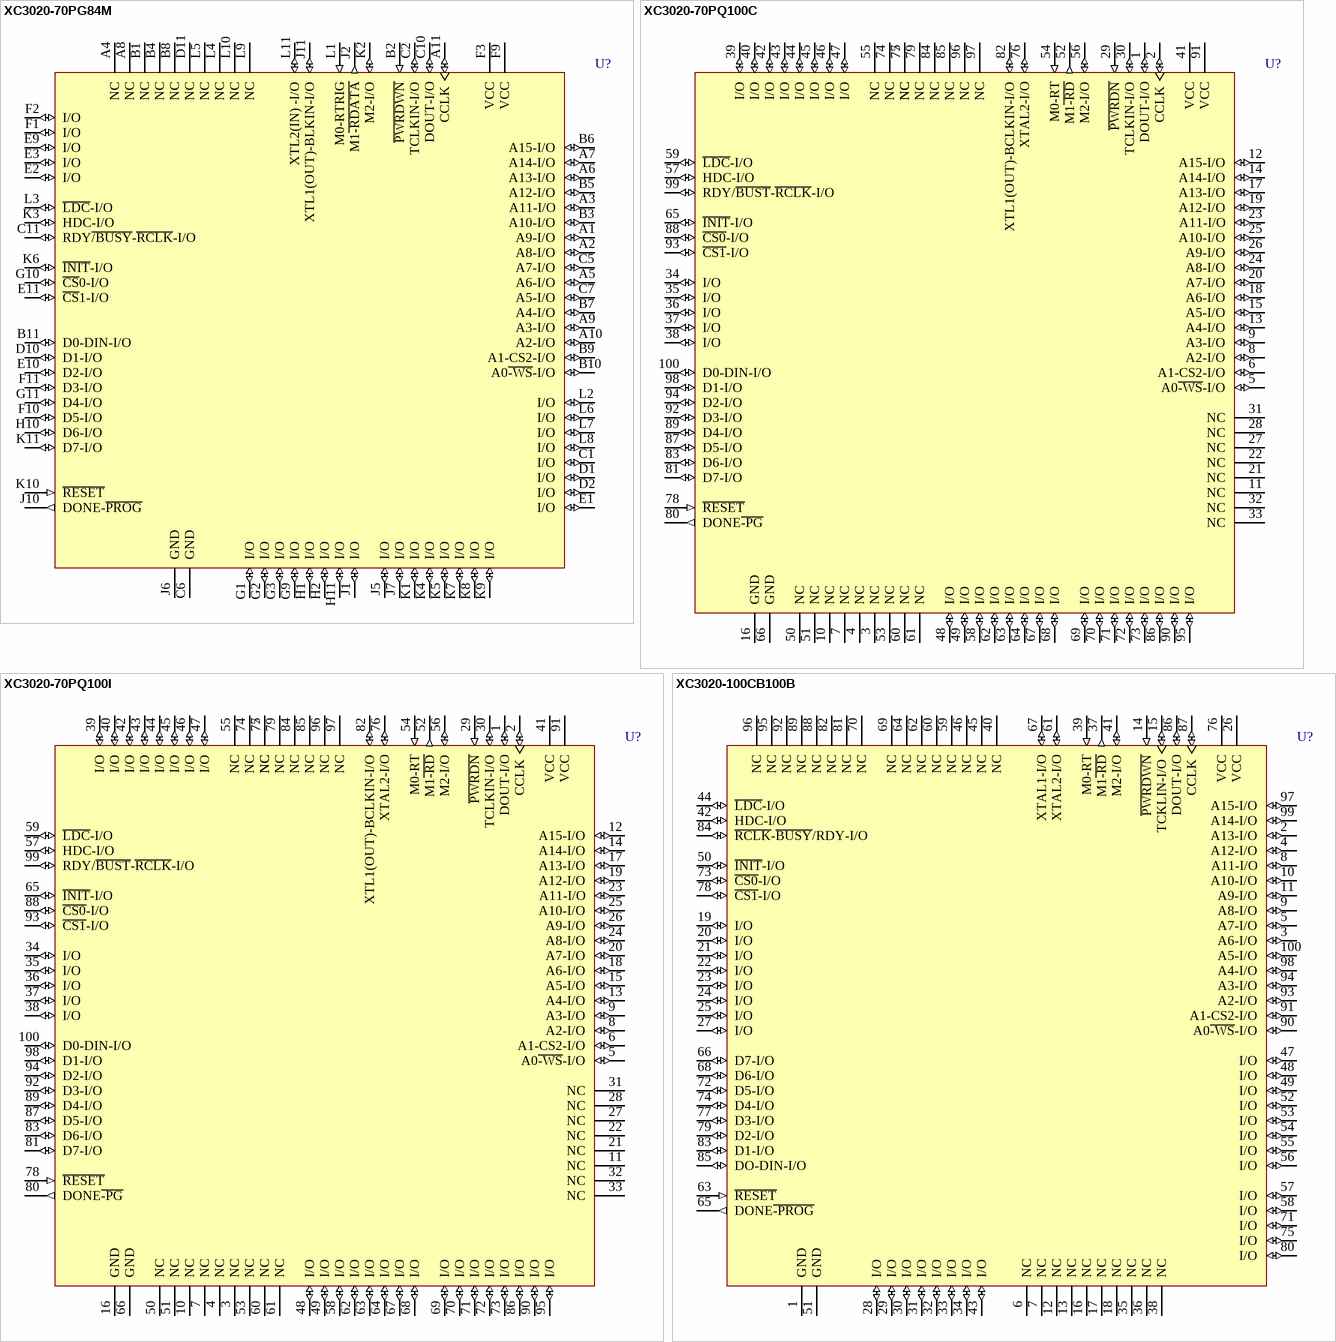
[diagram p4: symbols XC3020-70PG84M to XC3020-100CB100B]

## XC3020-70PG84M
designator U?
Logic Cell Array with 64 CLBs, with 64 I/O Pins, 84-Pin PGA, Military Grade; ComponentAvailability: Not for New Design
footprint PG84 (PGA, 85-Leads, Body 28x28mm, Pitch 2.54mm)
3D model XC3020-PG84 (84-Pin Ceramic Pin Grid Array (PG84))
pins: A1 A9-I/O (io), A2 A8-I/O (io), A3 A11-I/O (io), A4 NC, A5 A6-I/O (io), A6 A13-I/O (io), A7 A14-I/O (io), A8 NC, A9 A3-I/O (io), A10 A2-I/O (io), A11 CCLK (io), B1 NC, B2 ~{PWRDWN} (in), B3 A10-I/O (io), B4 NC, B5 A12-I/O (io), B6 A15-I/O (io), B7 A4-I/O (io), B8 NC, B9 A1-CS2-I/O (io), B10 A0~{-WS}-I/O (io), B11 D0-DIN-I/O (io), C1 I/O (io), C2 TCLKIN-I/O (io), C5 A7-I/O (io), C6 GND (power), C7 A5-I/O (io), C10 DOUT-I/O (io), C11 RDY~{/BUSY}-~{RCLK}-I/O (io), D1 I/O (io), D2 I/O (io), D10 D1-I/O (io), D11 NC, E1 I/O (io), E2 I/O (io), E3 I/O (io), E9 I/O (io), E10 D2-I/O (io), E11 ~{CS}1-I/O (io), F1 I/O (io), F2 I/O (io), F3 VCC (power), F9 VCC (power), F10 D5-I/O (io), F11 D3-I/O (io), G1 I/O (io), G2 I/O (io), G3 I/O (io), G9 I/O (io), G10 ~{CS}0-I/O (io), G11 D4-I/O (io), H1 I/O (io), H2 I/O (io), H10 D6-I/O (io), H11 I/O (io), J1 I/O (io), J2 M1~{-RDATA} (out), J5 I/O (io), J6 GND (power), J7 I/O (io), J10 DONE-~{PROG} (out), J11 XTL1(OUT)-BLKIN-I/O (io), K1 I/O (io), K2 M2-I/O (io), K3 HDC-I/O (io), K4 I/O (io), K5 I/O (io), K6 ~{INIT}-I/O (io), K7 I/O (io), K8 I/O (io), K9 I/O (io), K10 ~{RESET} (in), K11 D7-I/O (io), L1 M0-RTRIG (in), L2 I/O (io), L3 ~{LDC}-I/O (io), L4 NC, L5 NC, L6 I/O (io), L7 I/O (io), L8 I/O (io), L9 NC, L10 NC, L11 XTL2(IN) -I/O (io)

## XC3020-70PQ100C
designator U?
Logic Cell Array with 64 CLBs, with 64 I/O Pins, 100-Pin PQFP, Commercial Grade; ComponentAvailability: Not for New Design
footprint PQ100_N (QFP, 100-Leads, Body 20x14mm, Pitch 0.65mm, IPC Medium Density)
footprint PQ100_L (QFP, 100-Leads, Body 20x14mm, Pitch 0.65mm, IPC High Density)
footprint PQ100_M (QFP, 100-Leads, Body 20x14mm, Pitch 0.65mm, IPC Low Density)
3D model XC3020-PQ100 (100-Pin Plastic Quad Flat Pack (PQ100))
pins: 1 DOUT-I/O (io), 2 CCLK (io), 3 NC, 4 NC, 5 A0~{-WS}-I/O (io), 6 A1-CS2-I/O (io), 7 NC, 8 A2-I/O (io), 9 A3-I/O (io), 10 NC, 11 NC, 12 A15-I/O (io), 13 A4-I/O (io), 14 A14-I/O (io), 15 A5-I/O (io), 16 GND (power), 17 A13-I/O (io), 18 A6-I/O (io), 19 A12-I/O (io), 20 A7-I/O (io), 21 NC, 22 NC, 23 A11-I/O (io), 24 A8-I/O (io), 25 A10-I/O (io), 26 A9-I/O (io), 27 NC, 28 NC, 29 ~{PWRDN} (in), 30 TCLKIN-I/O (io), 31 NC, 32 NC, 33 NC, 34 I/O (io), 35 I/O (io), 36 I/O (io), 37 I/O (io), 38 I/O (io), 39 I/O (io), 40 I/O (io), 41 VCC (power), 42 I/O (io), 43 I/O (io), 44 I/O (io), 45 I/O (io), 46 I/O (io), 47 I/O (io), 48 I/O (io), 49 I/O (io), 50 NC, 51 NC, 52 M1~{-RD} (out), 53 NC, 54 M0-RT (in), 55 NC, 56 M2-I/O (io), 57 HDC-I/O (io), 58 I/O (io), 59 ~{LDC}-I/O (io), 60 NC, 61 NC, 62 I/O (io), 63 I/O (io), 64 I/O (io), 65 ~{INIT}-I/O (io), 66 GND (power), 67 I/O (io), 68 I/O (io), 69 I/O (io), 70 I/O (io), 71 I/O (io), 72 I/O (io), 73 I/O (io), 74 NC, 75 NC, 76 XTAL2-I/O (io), 77 NC, 78 ~{RESET} (in), 79 NC, 80 DONE~{-PG} (out), 81 D7-I/O (io), 82 XTL1(OUT)-BCLKIN-I/O (io), 83 D6-I/O (io), 84 NC, 85 NC, 86 I/O (io), 87 D5-I/O (io), 88 ~{CS0}-I/O (io), 89 D4-I/O (io), 90 I/O (io), 91 VCC (power), 92 D3-I/O (io), 93 ~{CS1}-I/O (io), 94 D2-I/O (io), 95 I/O (io), 96 NC, 97 NC, 98 D1-I/O (io), 99 RDY/~{BUST}-~{RCLK}-I/O (io), 100 D0-DIN-I/O (io)

## XC3020-70PQ100I
designator U?
Logic Cell Array with 64 CLBs, with 64 I/O Pins, 100-Pin PQFP, Industrial Grade; ComponentAvailability: Not for New Design
footprint PQ100_N (QFP, 100-Leads, Body 20x14mm, Pitch 0.65mm, IPC Medium Density)
footprint PQ100_L (QFP, 100-Leads, Body 20x14mm, Pitch 0.65mm, IPC High Density)
footprint PQ100_M (QFP, 100-Leads, Body 20x14mm, Pitch 0.65mm, IPC Low Density)
3D model XC3020-PQ100 (100-Pin Plastic Quad Flat Pack (PQ100))
pins: 1 DOUT-I/O (io), 2 CCLK (io), 3 NC, 4 NC, 5 A0~{-WS}-I/O (io), 6 A1-CS2-I/O (io), 7 NC, 8 A2-I/O (io), 9 A3-I/O (io), 10 NC, 11 NC, 12 A15-I/O (io), 13 A4-I/O (io), 14 A14-I/O (io), 15 A5-I/O (io), 16 GND (power), 17 A13-I/O (io), 18 A6-I/O (io), 19 A12-I/O (io), 20 A7-I/O (io), 21 NC, 22 NC, 23 A11-I/O (io), 24 A8-I/O (io), 25 A10-I/O (io), 26 A9-I/O (io), 27 NC, 28 NC, 29 ~{PWRDN} (in), 30 TCLKIN-I/O (io), 31 NC, 32 NC, 33 NC, 34 I/O (io), 35 I/O (io), 36 I/O (io), 37 I/O (io), 38 I/O (io), 39 I/O (io), 40 I/O (io), 41 VCC (power), 42 I/O (io), 43 I/O (io), 44 I/O (io), 45 I/O (io), 46 I/O (io), 47 I/O (io), 48 I/O (io), 49 I/O (io), 50 NC, 51 NC, 52 M1~{-RD} (out), 53 NC, 54 M0-RT (in), 55 NC, 56 M2-I/O (io), 57 HDC-I/O (io), 58 I/O (io), 59 ~{LDC}-I/O (io), 60 NC, 61 NC, 62 I/O (io), 63 I/O (io), 64 I/O (io), 65 ~{INIT}-I/O (io), 66 GND (power), 67 I/O (io), 68 I/O (io), 69 I/O (io), 70 I/O (io), 71 I/O (io), 72 I/O (io), 73 I/O (io), 74 NC, 75 NC, 76 XTAL2-I/O (io), 77 NC, 78 ~{RESET} (in), 79 NC, 80 DONE~{-PG} (out), 81 D7-I/O (io), 82 XTL1(OUT)-BCLKIN-I/O (io), 83 D6-I/O (io), 84 NC, 85 NC, 86 I/O (io), 87 D5-I/O (io), 88 ~{CS0}-I/O (io), 89 D4-I/O (io), 90 I/O (io), 91 VCC (power), 92 D3-I/O (io), 93 ~{CS1}-I/O (io), 94 D2-I/O (io), 95 I/O (io), 96 NC, 97 NC, 98 D1-I/O (io), 99 RDY/~{BUST}-~{RCLK}-I/O (io), 100 D0-DIN-I/O (io)

## XC3020-100CB100B
designator U?
Logic Cell Array with 64 CLBs, with 64 I/O Pins, 100-Pin CQFP, Military Class B Grade; ComponentAvailability: Not for New Design
footprint CB100_N (CQFP, 100-Leads, Body 19x19mm; Pitch 0.635mm, Gullwing Leadform, IPC Medium Density)
footprint CB100_L (CQFP, 100-Leads, Body 19x19mm; Pitch 0.635mm, Gullwing Leadform, IPC High Density)
footprint CB100_M (CQFP, 100-Leads, Body 19x19mm; Pitch 0.635mm, Gullwing Leadform, IPC Low Density)
3D model XC3020-CB100 (100-Pin Ceramic Brazed Quad Flat Pack (CB100))
pins: 1 GND (power), 2 A13-I/O (io), 3 A6-I/O (io), 4 A12-I/O (io), 5 A7-I/O (io), 6 NC, 7 NC, 8 A11-I/O (io), 9 A8-I/O (io), 10 A10-I/O (io), 11 A9-I/O (io), 12 NC, 13 NC, 14 ~{PWRDWN} (in), 15 TCKLIN-I/O (io), 16 NC, 17 NC, 18 NC, 19 I/O (io), 20 I/O (io), 21 I/O (io), 22 I/O (io), 23 I/O (io), 24 I/O (io), 25 I/O (io), 26 VCC (power), 27 I/O (io), 28 I/O (io), 29 I/O (io), 30 I/O (io), 31 I/O (io), 32 I/O (io), 33 I/O (io), 34 I/O (io), 35 NC, 36 NC, 37 M1~{-RD} (out), 38 NC, 39 M0-RT (in), 40 NC, 41 M2-I/O (io), 42 HDC-I/O (io), 43 I/O (io), 44 ~{LDC}-I/O (io), 45 NC, 46 NC, 47 I/O (io), 48 I/O (io), 49 I/O (io), 50 ~{INIT}-I/O (io), 51 GND (power), 52 I/O (io), 53 I/O (io), 54 I/O (io), 55 I/O (io), 56 I/O (io), 57 I/O (io), 58 I/O (io), 59 NC, 60 NC, 61 XTAL2-I/O (io), 62 NC, 63 ~{RESET} (in), 64 NC, 65 DONE~{-PROG} (out), 66 D7-I/O (io), 67 XTAL1-I/O (io), 68 D6-I/O (io), 69 NC, 70 NC, 71 I/O (io), 72 D5-I/O (io), 73 ~{CS0}-I/O (io), 74 D4-I/O (io), 75 I/O (io), 76 VCC (power), 77 D3-I/O (io), 78 ~{CS1}-I/O (io), 79 D2-I/O (io), 80 I/O (io), 81 NC, 82 NC, 83 D1-I/O (io), 84 ~{RCLK}-~{BUSY}/RDY-I/O (io), 85 DO-DIN-I/O (io), 86 DOUT-I/O (io), 87 CCLK (io), 88 NC, 89 NC, 90 A0~{-WS}-I/O (io), 91 A1-CS2-I/O (io), 92 NC, 93 A2-I/O (io), 94 A3-I/O (io), 95 NC, 96 NC, 97 A15-I/O (io), 98 A4-I/O (io), 99 A14-I/O (io), 100 A5-I/O (io)

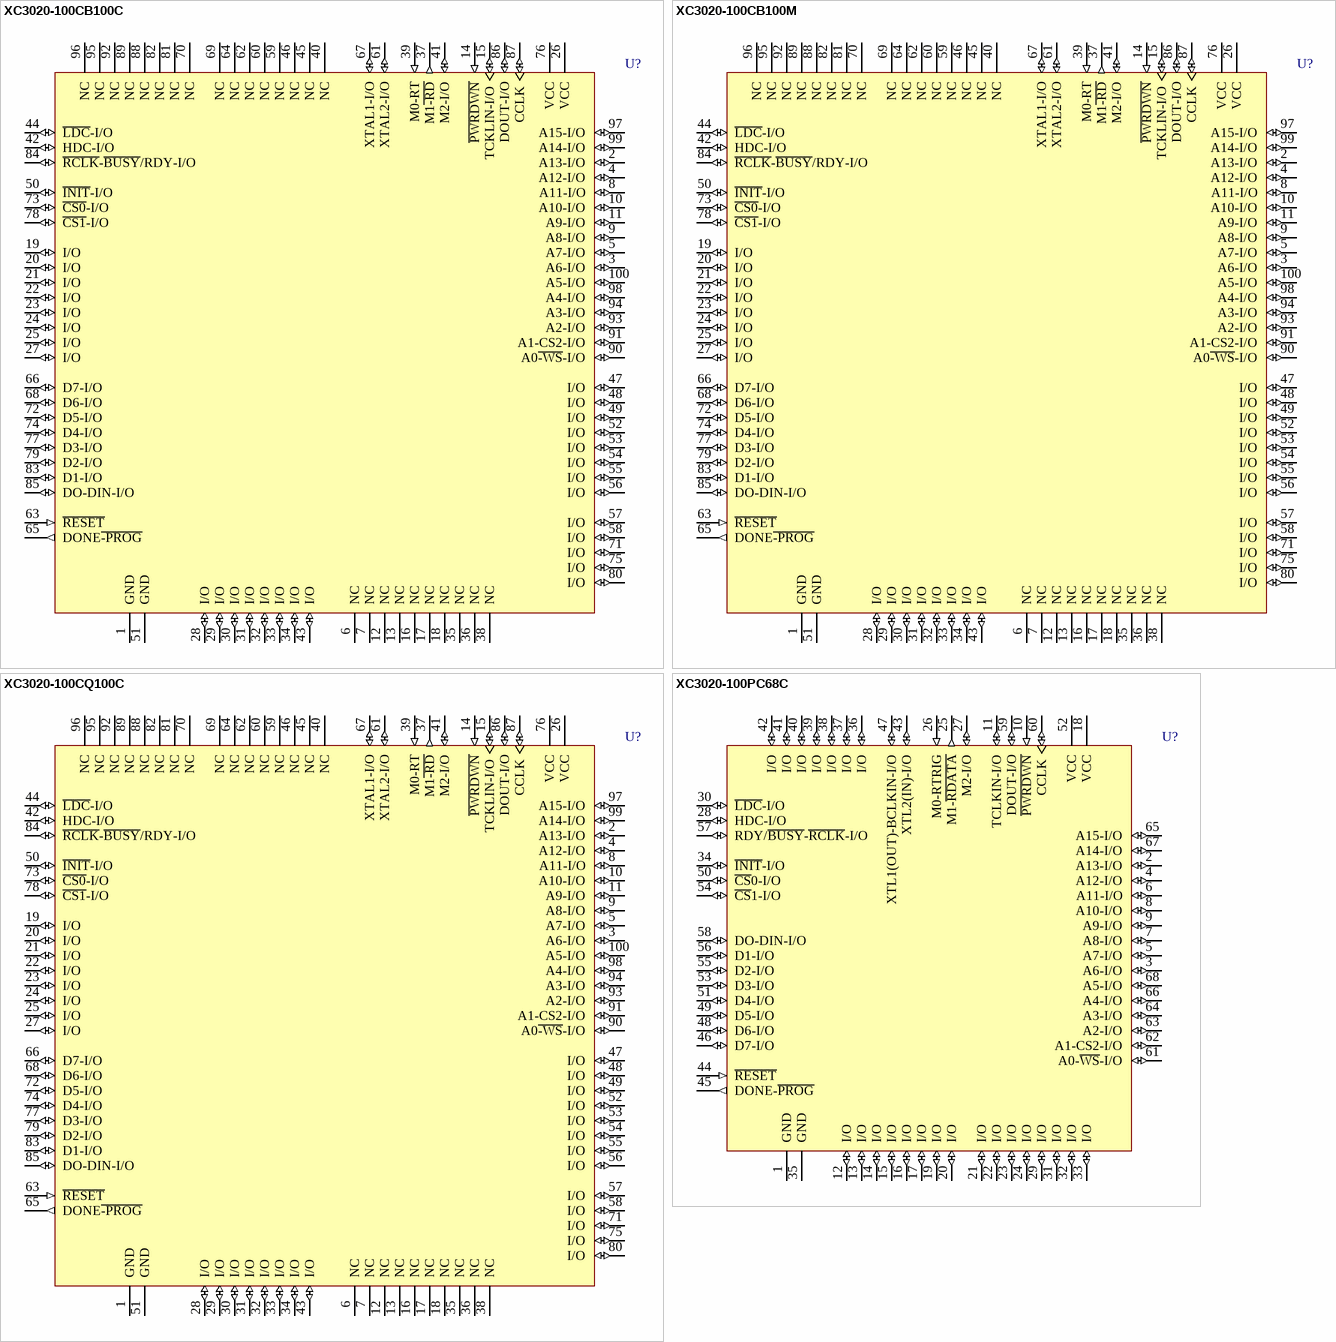
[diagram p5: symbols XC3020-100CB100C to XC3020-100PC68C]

## XC3020-100CB100C
designator U?
Logic Cell Array with 64 CLBs, with 64 I/O Pins, 100-Pin CQFP, Commercial Grade; ComponentAvailability: Not for New Design
footprint CB100_N (CQFP, 100-Leads, Body 19x19mm; Pitch 0.635mm, Gullwing Leadform, IPC Medium Density)
footprint CB100_L (CQFP, 100-Leads, Body 19x19mm; Pitch 0.635mm, Gullwing Leadform, IPC High Density)
footprint CB100_M (CQFP, 100-Leads, Body 19x19mm; Pitch 0.635mm, Gullwing Leadform, IPC Low Density)
3D model XC3020-CB100 (100-Pin Ceramic Brazed Quad Flat Pack (CB100))
pins: 1 GND (power), 2 A13-I/O (io), 3 A6-I/O (io), 4 A12-I/O (io), 5 A7-I/O (io), 6 NC, 7 NC, 8 A11-I/O (io), 9 A8-I/O (io), 10 A10-I/O (io), 11 A9-I/O (io), 12 NC, 13 NC, 14 ~{PWRDWN} (in), 15 TCKLIN-I/O (io), 16 NC, 17 NC, 18 NC, 19 I/O (io), 20 I/O (io), 21 I/O (io), 22 I/O (io), 23 I/O (io), 24 I/O (io), 25 I/O (io), 26 VCC (power), 27 I/O (io), 28 I/O (io), 29 I/O (io), 30 I/O (io), 31 I/O (io), 32 I/O (io), 33 I/O (io), 34 I/O (io), 35 NC, 36 NC, 37 M1~{-RD} (out), 38 NC, 39 M0-RT (in), 40 NC, 41 M2-I/O (io), 42 HDC-I/O (io), 43 I/O (io), 44 ~{LDC}-I/O (io), 45 NC, 46 NC, 47 I/O (io), 48 I/O (io), 49 I/O (io), 50 ~{INIT}-I/O (io), 51 GND (power), 52 I/O (io), 53 I/O (io), 54 I/O (io), 55 I/O (io), 56 I/O (io), 57 I/O (io), 58 I/O (io), 59 NC, 60 NC, 61 XTAL2-I/O (io), 62 NC, 63 ~{RESET} (in), 64 NC, 65 DONE~{-PROG} (out), 66 D7-I/O (io), 67 XTAL1-I/O (io), 68 D6-I/O (io), 69 NC, 70 NC, 71 I/O (io), 72 D5-I/O (io), 73 ~{CS0}-I/O (io), 74 D4-I/O (io), 75 I/O (io), 76 VCC (power), 77 D3-I/O (io), 78 ~{CS1}-I/O (io), 79 D2-I/O (io), 80 I/O (io), 81 NC, 82 NC, 83 D1-I/O (io), 84 ~{RCLK}-~{BUSY}/RDY-I/O (io), 85 DO-DIN-I/O (io), 86 DOUT-I/O (io), 87 CCLK (io), 88 NC, 89 NC, 90 A0~{-WS}-I/O (io), 91 A1-CS2-I/O (io), 92 NC, 93 A2-I/O (io), 94 A3-I/O (io), 95 NC, 96 NC, 97 A15-I/O (io), 98 A4-I/O (io), 99 A14-I/O (io), 100 A5-I/O (io)

## XC3020-100CB100M
designator U?
Logic Cell Array with 64 CLBs, with 64 I/O Pins, 100-Pin CQFP, Military Grade; ComponentAvailability: Not for New Design
footprint CB100_N (CQFP, 100-Leads, Body 19x19mm; Pitch 0.635mm, Gullwing Leadform, IPC Medium Density)
footprint CB100_L (CQFP, 100-Leads, Body 19x19mm; Pitch 0.635mm, Gullwing Leadform, IPC High Density)
footprint CB100_M (CQFP, 100-Leads, Body 19x19mm; Pitch 0.635mm, Gullwing Leadform, IPC Low Density)
3D model XC3020-CB100 (100-Pin Ceramic Brazed Quad Flat Pack (CB100))
pins: 1 GND (power), 2 A13-I/O (io), 3 A6-I/O (io), 4 A12-I/O (io), 5 A7-I/O (io), 6 NC, 7 NC, 8 A11-I/O (io), 9 A8-I/O (io), 10 A10-I/O (io), 11 A9-I/O (io), 12 NC, 13 NC, 14 ~{PWRDWN} (in), 15 TCKLIN-I/O (io), 16 NC, 17 NC, 18 NC, 19 I/O (io), 20 I/O (io), 21 I/O (io), 22 I/O (io), 23 I/O (io), 24 I/O (io), 25 I/O (io), 26 VCC (power), 27 I/O (io), 28 I/O (io), 29 I/O (io), 30 I/O (io), 31 I/O (io), 32 I/O (io), 33 I/O (io), 34 I/O (io), 35 NC, 36 NC, 37 M1~{-RD} (out), 38 NC, 39 M0-RT (in), 40 NC, 41 M2-I/O (io), 42 HDC-I/O (io), 43 I/O (io), 44 ~{LDC}-I/O (io), 45 NC, 46 NC, 47 I/O (io), 48 I/O (io), 49 I/O (io), 50 ~{INIT}-I/O (io), 51 GND (power), 52 I/O (io), 53 I/O (io), 54 I/O (io), 55 I/O (io), 56 I/O (io), 57 I/O (io), 58 I/O (io), 59 NC, 60 NC, 61 XTAL2-I/O (io), 62 NC, 63 ~{RESET} (in), 64 NC, 65 DONE~{-PROG} (out), 66 D7-I/O (io), 67 XTAL1-I/O (io), 68 D6-I/O (io), 69 NC, 70 NC, 71 I/O (io), 72 D5-I/O (io), 73 ~{CS0}-I/O (io), 74 D4-I/O (io), 75 I/O (io), 76 VCC (power), 77 D3-I/O (io), 78 ~{CS1}-I/O (io), 79 D2-I/O (io), 80 I/O (io), 81 NC, 82 NC, 83 D1-I/O (io), 84 ~{RCLK}-~{BUSY}/RDY-I/O (io), 85 DO-DIN-I/O (io), 86 DOUT-I/O (io), 87 CCLK (io), 88 NC, 89 NC, 90 A0~{-WS}-I/O (io), 91 A1-CS2-I/O (io), 92 NC, 93 A2-I/O (io), 94 A3-I/O (io), 95 NC, 96 NC, 97 A15-I/O (io), 98 A4-I/O (io), 99 A14-I/O (io), 100 A5-I/O (io)

## XC3020-100CQ100C
designator U?
Logic Cell Array with 64 CLBs, with 64 I/O Pins, 100-Pin CQFP, Commercial Grade; ComponentAvailability: Not for New Design
footprint CB100_N (CQFP, 100-Leads, Body 19x19mm; Pitch 0.635mm, Gullwing Leadform, IPC Medium Density)
footprint CB100_L (CQFP, 100-Leads, Body 19x19mm; Pitch 0.635mm, Gullwing Leadform, IPC High Density)
footprint CB100_M (CQFP, 100-Leads, Body 19x19mm; Pitch 0.635mm, Gullwing Leadform, IPC Low Density)
3D model XC3020-CB100 (100-Pin Ceramic Brazed Quad Flat Pack (CB100))
pins: 1 GND (power), 2 A13-I/O (io), 3 A6-I/O (io), 4 A12-I/O (io), 5 A7-I/O (io), 6 NC, 7 NC, 8 A11-I/O (io), 9 A8-I/O (io), 10 A10-I/O (io), 11 A9-I/O (io), 12 NC, 13 NC, 14 ~{PWRDWN} (in), 15 TCKLIN-I/O (io), 16 NC, 17 NC, 18 NC, 19 I/O (io), 20 I/O (io), 21 I/O (io), 22 I/O (io), 23 I/O (io), 24 I/O (io), 25 I/O (io), 26 VCC (power), 27 I/O (io), 28 I/O (io), 29 I/O (io), 30 I/O (io), 31 I/O (io), 32 I/O (io), 33 I/O (io), 34 I/O (io), 35 NC, 36 NC, 37 M1~{-RD} (out), 38 NC, 39 M0-RT (in), 40 NC, 41 M2-I/O (io), 42 HDC-I/O (io), 43 I/O (io), 44 ~{LDC}-I/O (io), 45 NC, 46 NC, 47 I/O (io), 48 I/O (io), 49 I/O (io), 50 ~{INIT}-I/O (io), 51 GND (power), 52 I/O (io), 53 I/O (io), 54 I/O (io), 55 I/O (io), 56 I/O (io), 57 I/O (io), 58 I/O (io), 59 NC, 60 NC, 61 XTAL2-I/O (io), 62 NC, 63 ~{RESET} (in), 64 NC, 65 DONE~{-PROG} (out), 66 D7-I/O (io), 67 XTAL1-I/O (io), 68 D6-I/O (io), 69 NC, 70 NC, 71 I/O (io), 72 D5-I/O (io), 73 ~{CS0}-I/O (io), 74 D4-I/O (io), 75 I/O (io), 76 VCC (power), 77 D3-I/O (io), 78 ~{CS1}-I/O (io), 79 D2-I/O (io), 80 I/O (io), 81 NC, 82 NC, 83 D1-I/O (io), 84 ~{RCLK}-~{BUSY}/RDY-I/O (io), 85 DO-DIN-I/O (io), 86 DOUT-I/O (io), 87 CCLK (io), 88 NC, 89 NC, 90 A0~{-WS}-I/O (io), 91 A1-CS2-I/O (io), 92 NC, 93 A2-I/O (io), 94 A3-I/O (io), 95 NC, 96 NC, 97 A15-I/O (io), 98 A4-I/O (io), 99 A14-I/O (io), 100 A5-I/O (io)

## XC3020-100PC68C
designator U?
Logic Cell Array with 64 CLBs, with 58 I/O Pins, 68-Pin PLCC, Commercial Grade; ComponentAvailability: Not for New Design
footprint PC68_N (Leaded Chip Carrier, 68-Leads, Body 24x24mm, Pitch 1.27mm, IPC Medium Density)
footprint PC68_L (Leaded Chip Carrier, 68-Leads, Body 24x24mm, Pitch 1.27mm, IPC High Density)
footprint PC68_M (Leaded Chip Carrier, 68-Leads, Body 24x24mm, Pitch 1.27mm, IPC Low Density)
3D model XC3020-PC68 (68-Pin Plastic Leaded Chip Carrier (PC68))
pins: 1 GND (power), 2 A13-I/O (io), 3 A6-I/O (io), 4 A12-I/O (io), 5 A7-I/O (io), 6 A11-I/O (io), 7 A8-I/O (io), 8 A10-I/O (io), 9 A9-I/O (io), 10 ~{PWRDWN} (in), 11 TCLKIN-I/O (io), 12 I/O (io), 13 I/O (io), 14 I/O (io), 15 I/O (io), 16 I/O (io), 17 I/O (io), 18 VCC (power), 19 I/O (io), 20 I/O (io), 21 I/O (io), 22 I/O (io), 23 I/O (io), 24 I/O (io), 25 M1-~{RDATA} (out), 26 M0-RTRIG (in), 27 M2-I/O (io), 28 HDC-I/O (io), 29 I/O (io), 30 ~{LDC}-I/O (io), 31 I/O (io), 32 I/O (io), 33 I/O (io), 34 ~{INIT}-I/O (io), 35 GND (power), 36 I/O (io), 37 I/O (io), 38 I/O (io), 39 I/O (io), 40 I/O (io), 41 I/O (io), 42 I/O (io), 43 XTL2(IN)-I/O (io), 44 ~{RESET} (in), 45 DONE-~{PROG} (out), 46 D7-I/O (io), 47 XTL1(OUT)-BCLKIN-I/O (io), 48 D6-I/O (io), 49 D5-I/O (io), 50 ~{CS}0-I/O (io), 51 D4-I/O (io), 52 VCC (power), 53 D3-I/O (io), 54 ~{CS}1-I/O (io), 55 D2-I/O (io), 56 D1-I/O (io), 57 RDY/~{BUSY}-~{RCLK}-I/O (io), 58 DO-DIN-I/O (io), 59 DOUT-I/O (io), 60 CCLK (io), 61 A0-~{WS}-I/O (io), 62 A1-CS2-I/O (io), 63 A2-I/O (io), 64 A3-I/O (io), 65 A15-I/O (io), 66 A4-I/O (io), 67 A14-I/O (io), 68 A5-I/O (io)

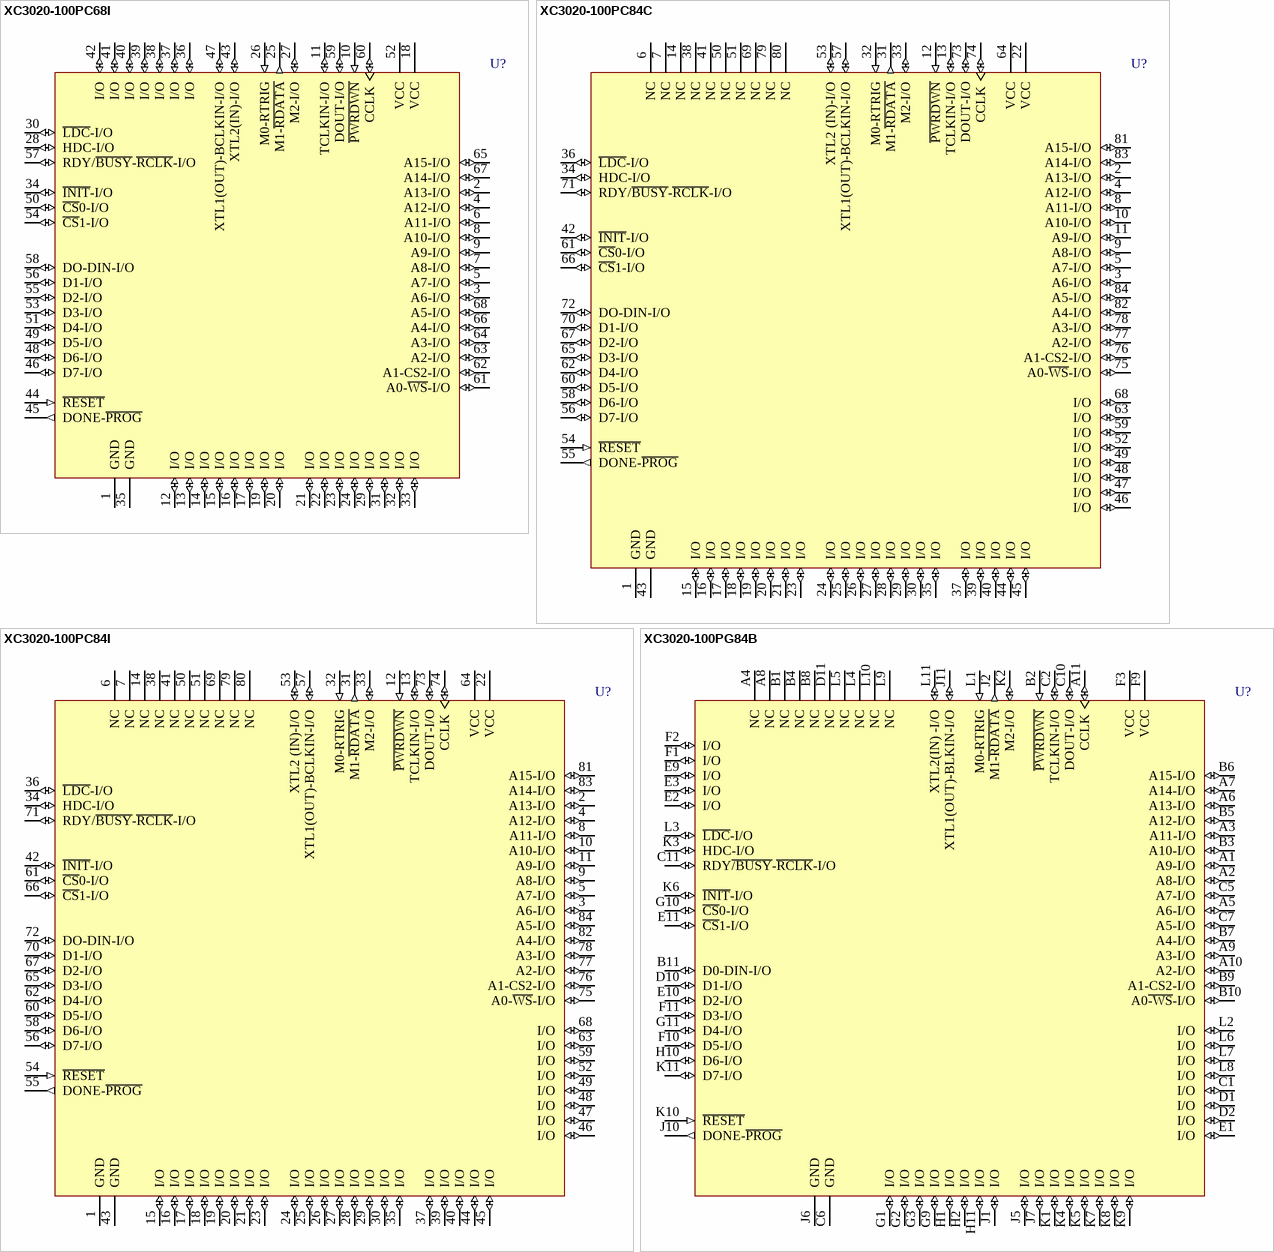
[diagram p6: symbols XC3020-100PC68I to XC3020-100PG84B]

## XC3020-100PC68I
designator U?
Logic Cell Array with 64 CLBs, with 58 I/O Pins, 68-Pin PLCC, Industrial Grade; ComponentAvailability: Not for New Design
footprint PC68_N (Leaded Chip Carrier, 68-Leads, Body 24x24mm, Pitch 1.27mm, IPC Medium Density)
footprint PC68_L (Leaded Chip Carrier, 68-Leads, Body 24x24mm, Pitch 1.27mm, IPC High Density)
footprint PC68_M (Leaded Chip Carrier, 68-Leads, Body 24x24mm, Pitch 1.27mm, IPC Low Density)
3D model XC3020-PC68 (68-Pin Plastic Leaded Chip Carrier (PC68))
pins: 1 GND (power), 2 A13-I/O (io), 3 A6-I/O (io), 4 A12-I/O (io), 5 A7-I/O (io), 6 A11-I/O (io), 7 A8-I/O (io), 8 A10-I/O (io), 9 A9-I/O (io), 10 ~{PWRDWN} (in), 11 TCLKIN-I/O (io), 12 I/O (io), 13 I/O (io), 14 I/O (io), 15 I/O (io), 16 I/O (io), 17 I/O (io), 18 VCC (power), 19 I/O (io), 20 I/O (io), 21 I/O (io), 22 I/O (io), 23 I/O (io), 24 I/O (io), 25 M1-~{RDATA} (out), 26 M0-RTRIG (in), 27 M2-I/O (io), 28 HDC-I/O (io), 29 I/O (io), 30 ~{LDC}-I/O (io), 31 I/O (io), 32 I/O (io), 33 I/O (io), 34 ~{INIT}-I/O (io), 35 GND (power), 36 I/O (io), 37 I/O (io), 38 I/O (io), 39 I/O (io), 40 I/O (io), 41 I/O (io), 42 I/O (io), 43 XTL2(IN)-I/O (io), 44 ~{RESET} (in), 45 DONE-~{PROG} (out), 46 D7-I/O (io), 47 XTL1(OUT)-BCLKIN-I/O (io), 48 D6-I/O (io), 49 D5-I/O (io), 50 ~{CS}0-I/O (io), 51 D4-I/O (io), 52 VCC (power), 53 D3-I/O (io), 54 ~{CS}1-I/O (io), 55 D2-I/O (io), 56 D1-I/O (io), 57 RDY/~{BUSY}-~{RCLK}-I/O (io), 58 DO-DIN-I/O (io), 59 DOUT-I/O (io), 60 CCLK (io), 61 A0-~{WS}-I/O (io), 62 A1-CS2-I/O (io), 63 A2-I/O (io), 64 A3-I/O (io), 65 A15-I/O (io), 66 A4-I/O (io), 67 A14-I/O (io), 68 A5-I/O (io)

## XC3020-100PC84C
designator U?
Logic Cell Array with 64 CLBs, with 64 I/O Pins, 84-Pin PLCC, Commercial Grade; ComponentAvailability: Not for New Design
footprint PC84_N (Leaded Chip Carrier, 84-Leads, Body 29.3x29.3mm, Pitch 1.27mm, IPC Medium Density)
footprint PC84_L (Leaded Chip Carrier, 84-Leads, Body 29.3x29.3mm, Pitch 1.27mm, IPC High Density)
footprint PC84_M (Leaded Chip Carrier, 84-Leads, Body 29.3x29.3mm, Pitch 1.27mm, IPC Low Density)
3D model XC3020-PC84 (84-Pin Plastic Leaded Chip Carrier (PC84))
pins: 1 GND (power), 2 A13-I/O (io), 3 A6-I/O (io), 4 A12-I/O (io), 5 A7-I/O (io), 6 NC, 7 NC, 8 A11-I/O (io), 9 A8-I/O (io), 10 A10-I/O (io), 11 A9-I/O (io), 12 ~{PWRDWN} (in), 13 TCLKIN-I/O (io), 14 NC, 15 I/O (io), 16 I/O (io), 17 I/O (io), 18 I/O (io), 19 I/O (io), 20 I/O (io), 21 I/O (io), 22 VCC (power), 23 I/O (io), 24 I/O (io), 25 I/O (io), 26 I/O (io), 27 I/O (io), 28 I/O (io), 29 I/O (io), 30 I/O (io), 31 M1-~{RDATA} (out), 32 M0-RTRIG (in), 33 M2-I/O (io), 34 HDC-I/O (io), 35 I/O (io), 36 ~{LDC}-I/O (io), 37 I/O (io), 38 NC, 39 I/O (io), 40 I/O (io), 41 NC, 42 ~{INIT}-I/O (io), 43 GND (power), 44 I/O (io), 45 I/O (io), 46 I/O (io), 47 I/O (io), 48 I/O (io), 49 I/O (io), 50 NC, 51 NC, 52 I/O (io), 53 XTL2 (IN)-I/O (io), 54 ~{RESET} (in), 55 DONE-~{PROG} (out), 56 D7-I/O (io), 57 XTL1(OUT)-BCLKIN-I/O (io), 58 D6-I/O (io), 59 I/O (io), 60 D5-I/O (io), 61 ~{CS}0-I/O (io), 62 D4-I/O (io), 63 I/O (io), 64 VCC (power), 65 D3-I/O (io), 66 ~{CS}1-I/O (io), 67 D2-I/O (io), 68 I/O (io), 69 NC, 70 D1-I/O (io), 71 RDY/~{BUSY}-~{RCLK}-I/O (io), 72 DO-DIN-I/O (io), 73 DOUT-I/O (io), 74 CCLK (io), 75 A0-~{WS}-I/O (io), 76 A1-CS2-I/O (io), 77 A2-I/O (io), 78 A3-I/O (io), 79 NC, 80 NC, 81 A15-I/O (io), 82 A4-I/O (io), 83 A14-I/O (io), 84 A5-I/O (io)

## XC3020-100PC84I
designator U?
Logic Cell Array with 64 CLBs, with 64 I/O Pins, 84-Pin PLCC, Industrial Grade; ComponentAvailability: Not for New Design
footprint PC84_N (Leaded Chip Carrier, 84-Leads, Body 29.3x29.3mm, Pitch 1.27mm, IPC Medium Density)
footprint PC84_L (Leaded Chip Carrier, 84-Leads, Body 29.3x29.3mm, Pitch 1.27mm, IPC High Density)
footprint PC84_M (Leaded Chip Carrier, 84-Leads, Body 29.3x29.3mm, Pitch 1.27mm, IPC Low Density)
3D model XC3020-PC84 (84-Pin Plastic Leaded Chip Carrier (PC84))
pins: 1 GND (power), 2 A13-I/O (io), 3 A6-I/O (io), 4 A12-I/O (io), 5 A7-I/O (io), 6 NC, 7 NC, 8 A11-I/O (io), 9 A8-I/O (io), 10 A10-I/O (io), 11 A9-I/O (io), 12 ~{PWRDWN} (in), 13 TCLKIN-I/O (io), 14 NC, 15 I/O (io), 16 I/O (io), 17 I/O (io), 18 I/O (io), 19 I/O (io), 20 I/O (io), 21 I/O (io), 22 VCC (power), 23 I/O (io), 24 I/O (io), 25 I/O (io), 26 I/O (io), 27 I/O (io), 28 I/O (io), 29 I/O (io), 30 I/O (io), 31 M1-~{RDATA} (out), 32 M0-RTRIG (in), 33 M2-I/O (io), 34 HDC-I/O (io), 35 I/O (io), 36 ~{LDC}-I/O (io), 37 I/O (io), 38 NC, 39 I/O (io), 40 I/O (io), 41 NC, 42 ~{INIT}-I/O (io), 43 GND (power), 44 I/O (io), 45 I/O (io), 46 I/O (io), 47 I/O (io), 48 I/O (io), 49 I/O (io), 50 NC, 51 NC, 52 I/O (io), 53 XTL2 (IN)-I/O (io), 54 ~{RESET} (in), 55 DONE-~{PROG} (out), 56 D7-I/O (io), 57 XTL1(OUT)-BCLKIN-I/O (io), 58 D6-I/O (io), 59 I/O (io), 60 D5-I/O (io), 61 ~{CS}0-I/O (io), 62 D4-I/O (io), 63 I/O (io), 64 VCC (power), 65 D3-I/O (io), 66 ~{CS}1-I/O (io), 67 D2-I/O (io), 68 I/O (io), 69 NC, 70 D1-I/O (io), 71 RDY/~{BUSY}-~{RCLK}-I/O (io), 72 DO-DIN-I/O (io), 73 DOUT-I/O (io), 74 CCLK (io), 75 A0-~{WS}-I/O (io), 76 A1-CS2-I/O (io), 77 A2-I/O (io), 78 A3-I/O (io), 79 NC, 80 NC, 81 A15-I/O (io), 82 A4-I/O (io), 83 A14-I/O (io), 84 A5-I/O (io)

## XC3020-100PG84B
designator U?
Logic Cell Array with 64 CLBs, with 64 I/O Pins, 84-Pin PGA, Military Class B Grade; ComponentAvailability: Not for New Design
footprint PG84 (PGA, 85-Leads, Body 28x28mm, Pitch 2.54mm)
3D model XC3020-PG84 (84-Pin Ceramic Pin Grid Array (PG84))
pins: A1 A9-I/O (io), A2 A8-I/O (io), A3 A11-I/O (io), A4 NC, A5 A6-I/O (io), A6 A13-I/O (io), A7 A14-I/O (io), A8 NC, A9 A3-I/O (io), A10 A2-I/O (io), A11 CCLK (io), B1 NC, B2 ~{PWRDWN} (in), B3 A10-I/O (io), B4 NC, B5 A12-I/O (io), B6 A15-I/O (io), B7 A4-I/O (io), B8 NC, B9 A1-CS2-I/O (io), B10 A0~{-WS}-I/O (io), B11 D0-DIN-I/O (io), C1 I/O (io), C2 TCLKIN-I/O (io), C5 A7-I/O (io), C6 GND (power), C7 A5-I/O (io), C10 DOUT-I/O (io), C11 RDY~{/BUSY}-~{RCLK}-I/O (io), D1 I/O (io), D2 I/O (io), D10 D1-I/O (io), D11 NC, E1 I/O (io), E2 I/O (io), E3 I/O (io), E9 I/O (io), E10 D2-I/O (io), E11 ~{CS}1-I/O (io), F1 I/O (io), F2 I/O (io), F3 VCC (power), F9 VCC (power), F10 D5-I/O (io), F11 D3-I/O (io), G1 I/O (io), G2 I/O (io), G3 I/O (io), G9 I/O (io), G10 ~{CS}0-I/O (io), G11 D4-I/O (io), H1 I/O (io), H2 I/O (io), H10 D6-I/O (io), H11 I/O (io), J1 I/O (io), J2 M1~{-RDATA} (out), J5 I/O (io), J6 GND (power), J7 I/O (io), J10 DONE-~{PROG} (out), J11 XTL1(OUT)-BLKIN-I/O (io), K1 I/O (io), K2 M2-I/O (io), K3 HDC-I/O (io), K4 I/O (io), K5 I/O (io), K6 ~{INIT}-I/O (io), K7 I/O (io), K8 I/O (io), K9 I/O (io), K10 ~{RESET} (in), K11 D7-I/O (io), L1 M0-RTRIG (in), L2 I/O (io), L3 ~{LDC}-I/O (io), L4 NC, L5 NC, L6 I/O (io), L7 I/O (io), L8 I/O (io), L9 NC, L10 NC, L11 XTL2(IN) -I/O (io)

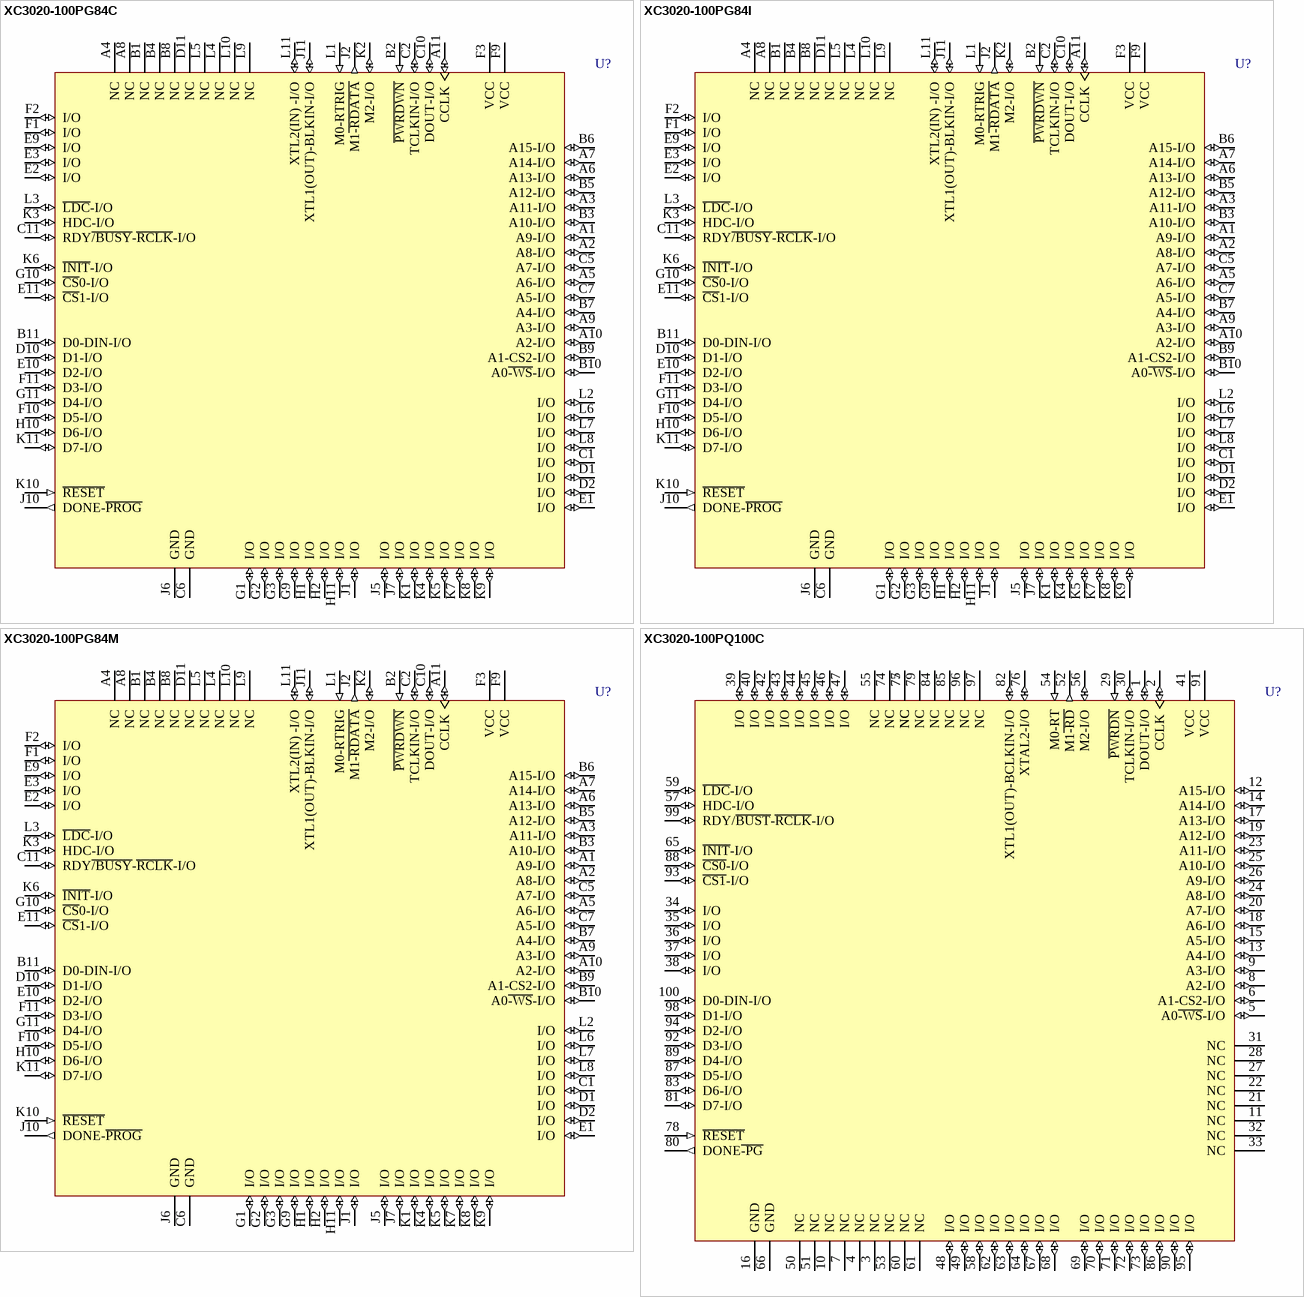
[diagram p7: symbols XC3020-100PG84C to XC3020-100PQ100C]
